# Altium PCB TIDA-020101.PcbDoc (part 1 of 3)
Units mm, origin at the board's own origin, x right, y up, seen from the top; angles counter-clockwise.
Board outline 55 x 55 mm, 4 copper layers (Top Layer 1, Top Layer, Bottom Layer, Bottom Layer 1), stack 1.647 mm thick; 151 components, 88 nets, 395 pads, 362 vias.
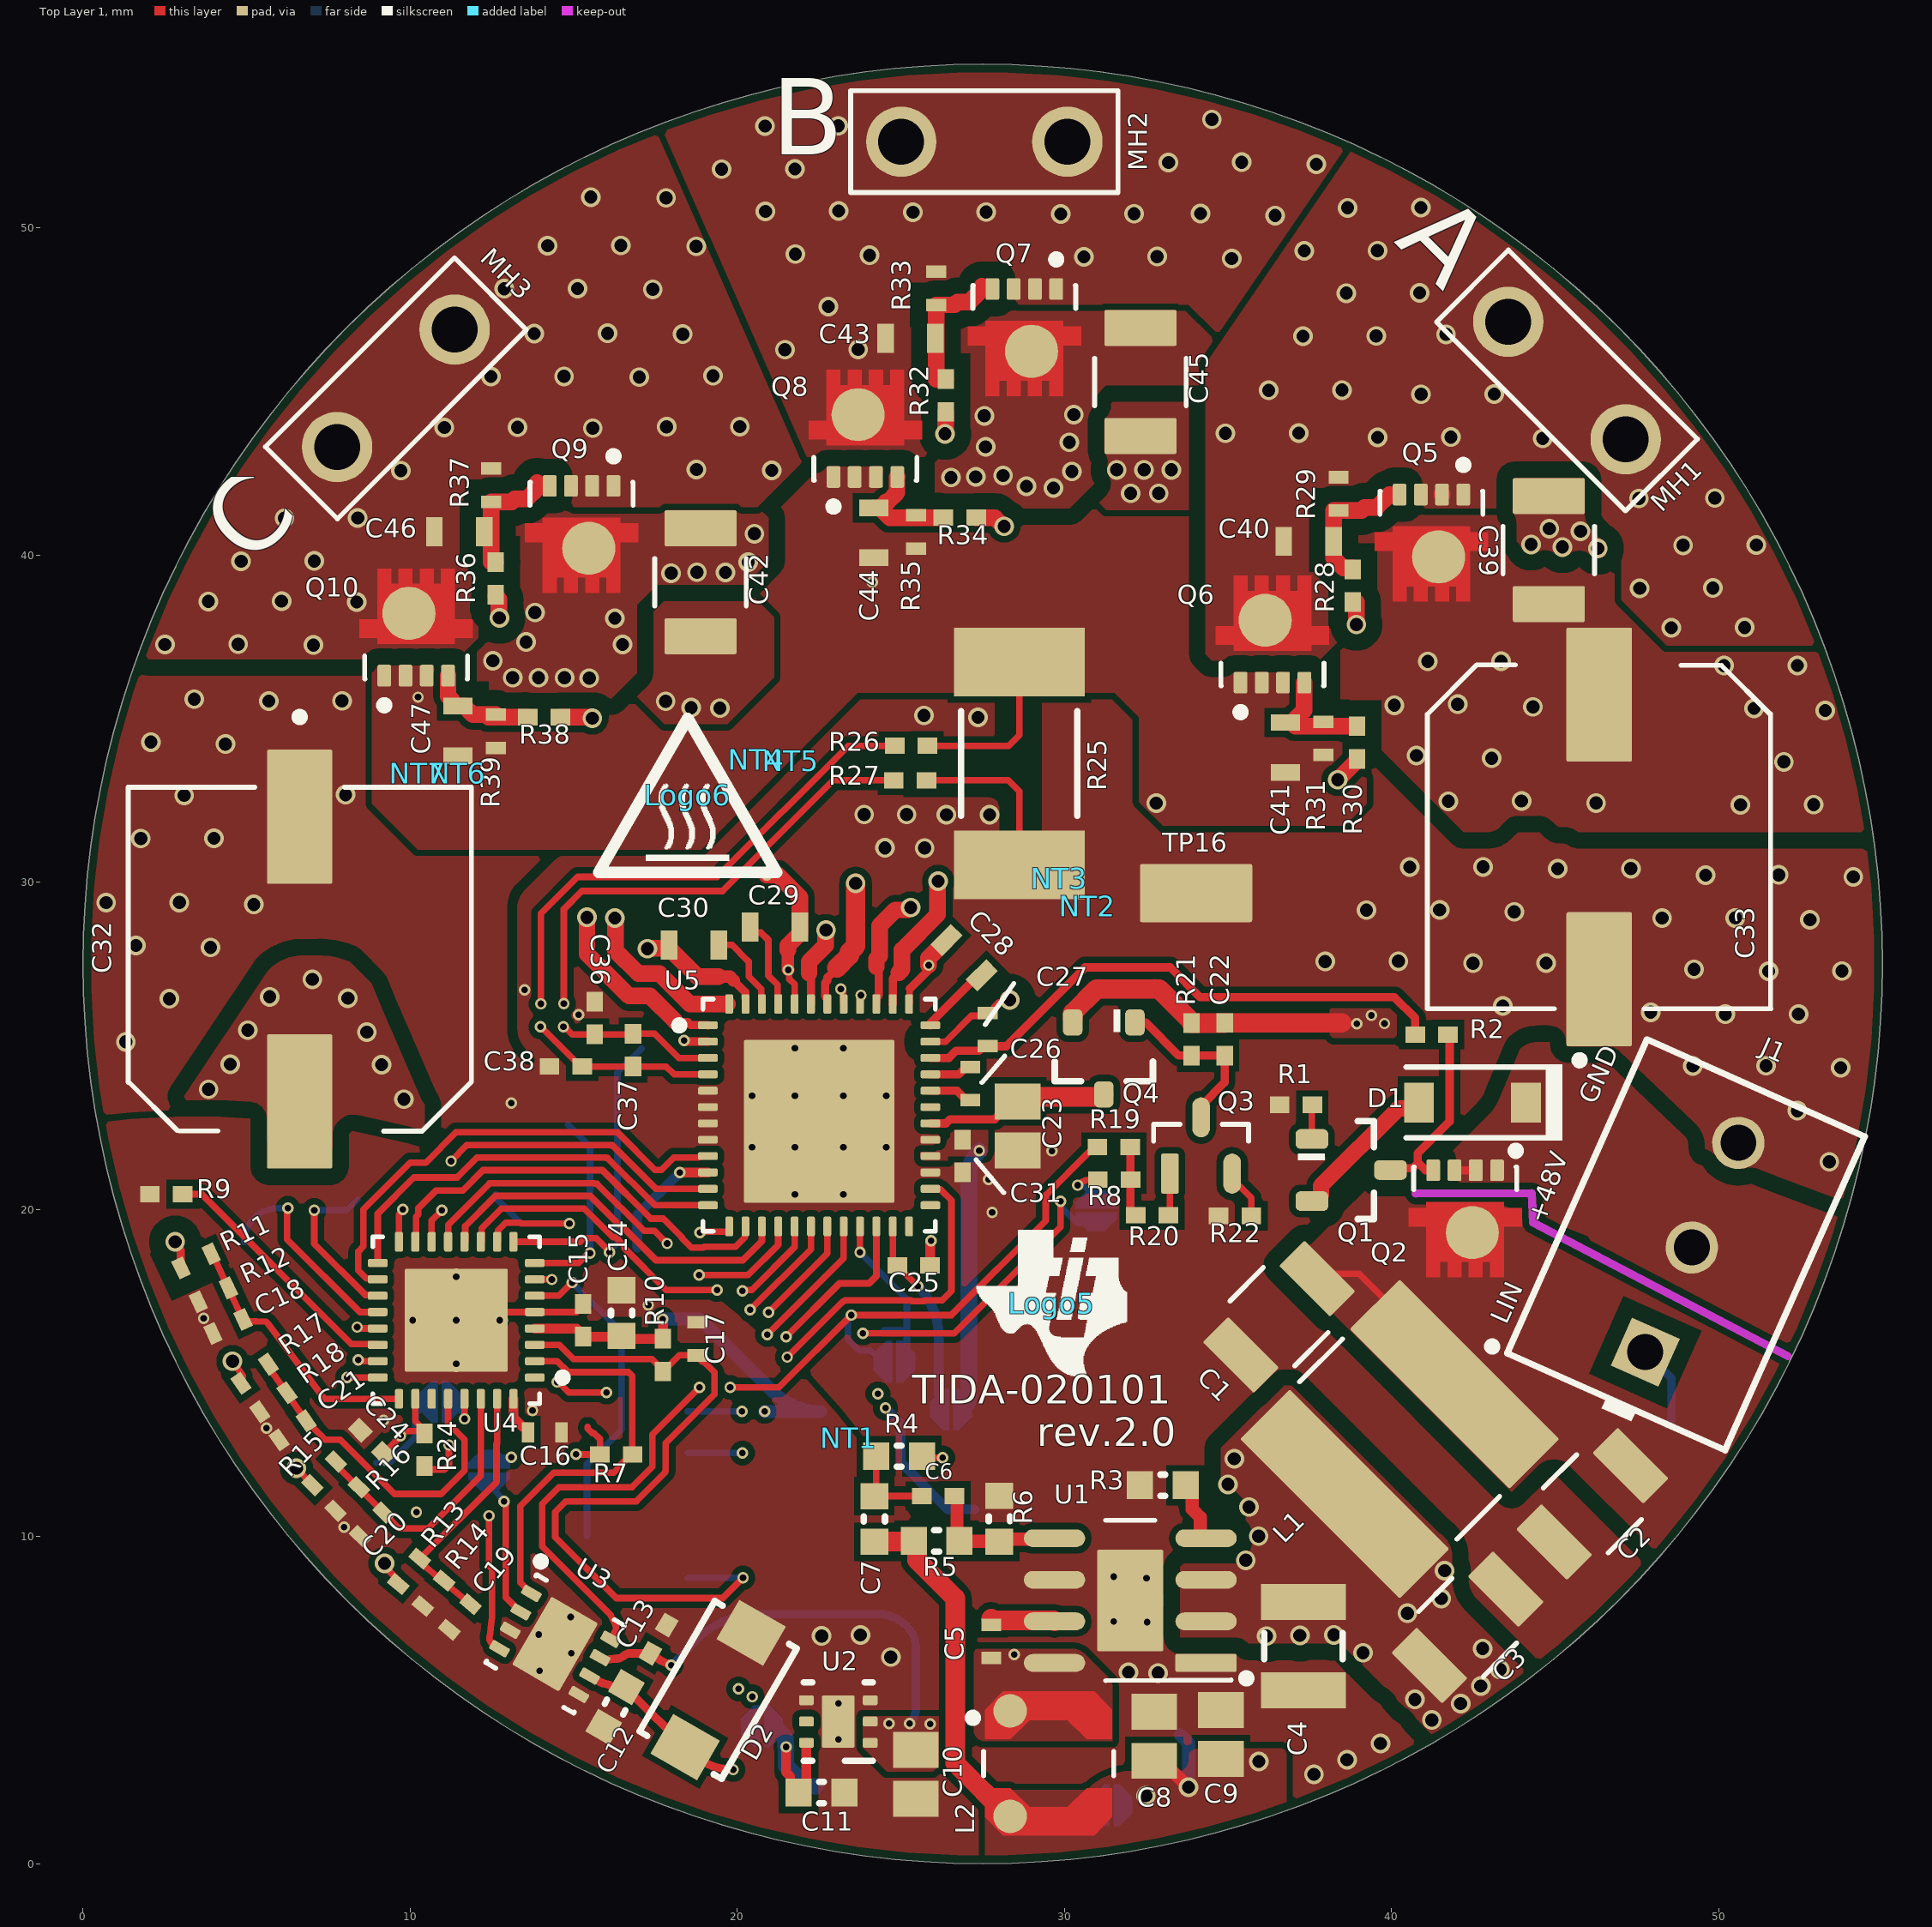
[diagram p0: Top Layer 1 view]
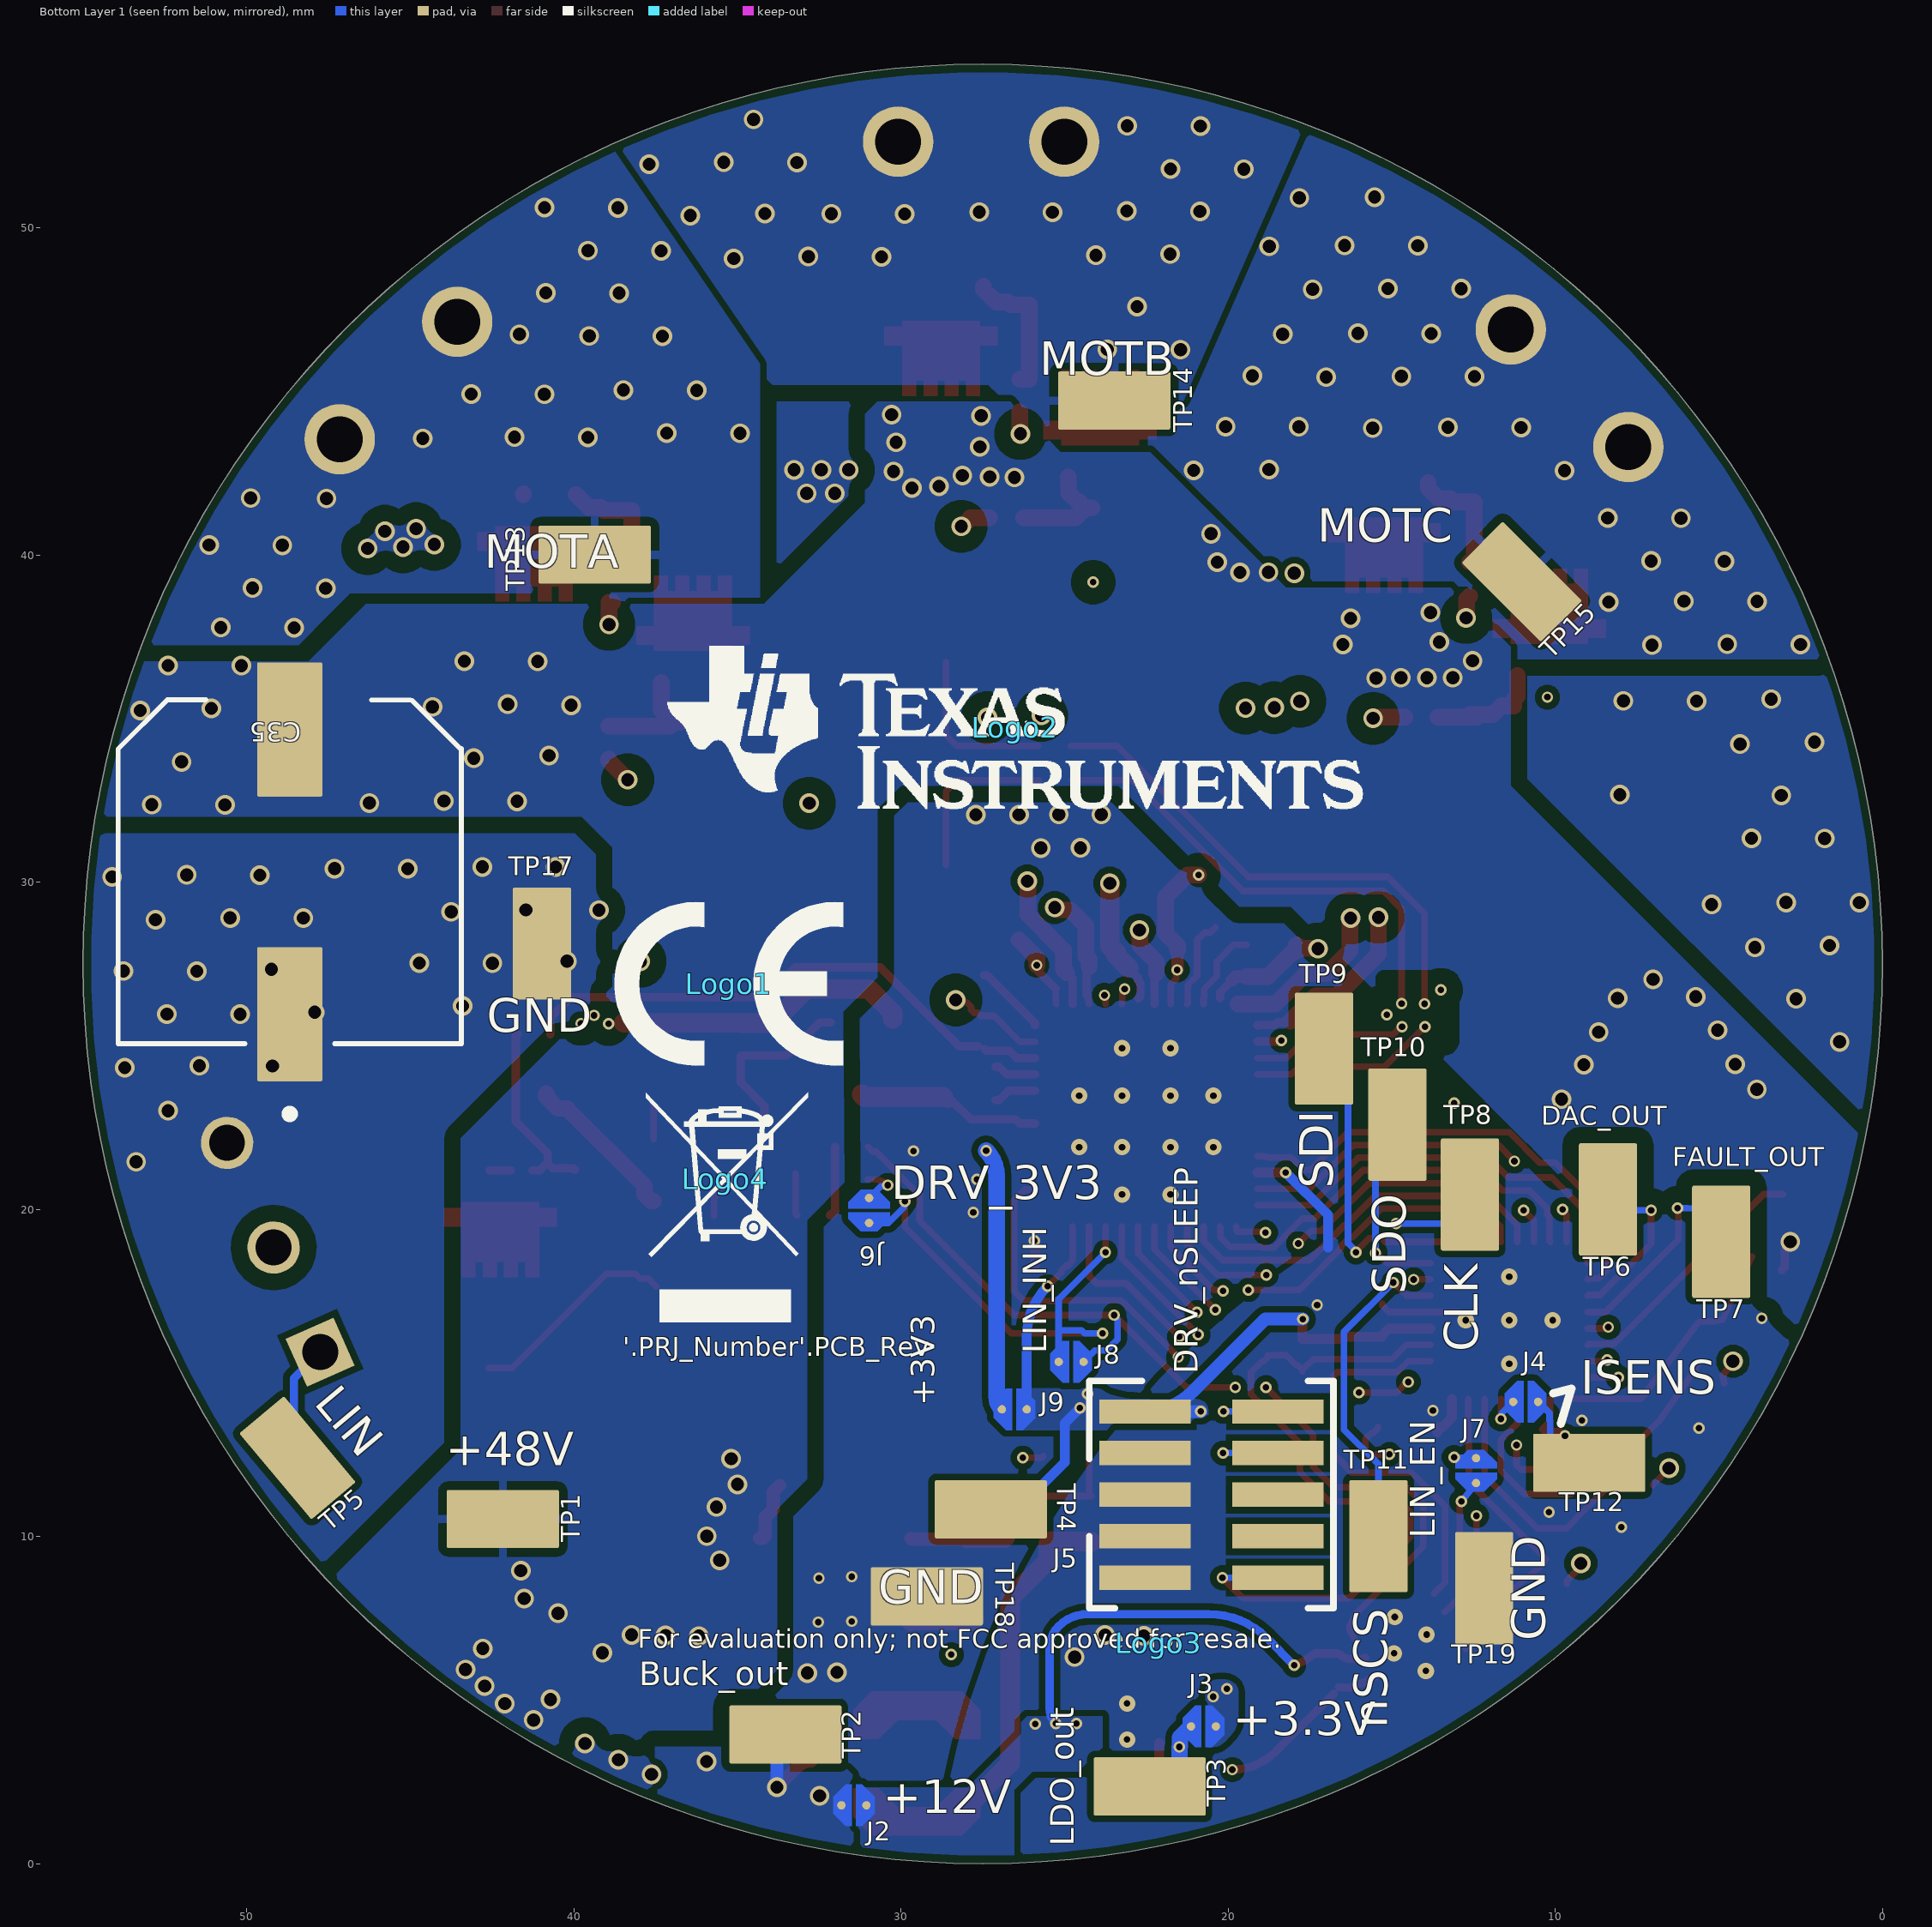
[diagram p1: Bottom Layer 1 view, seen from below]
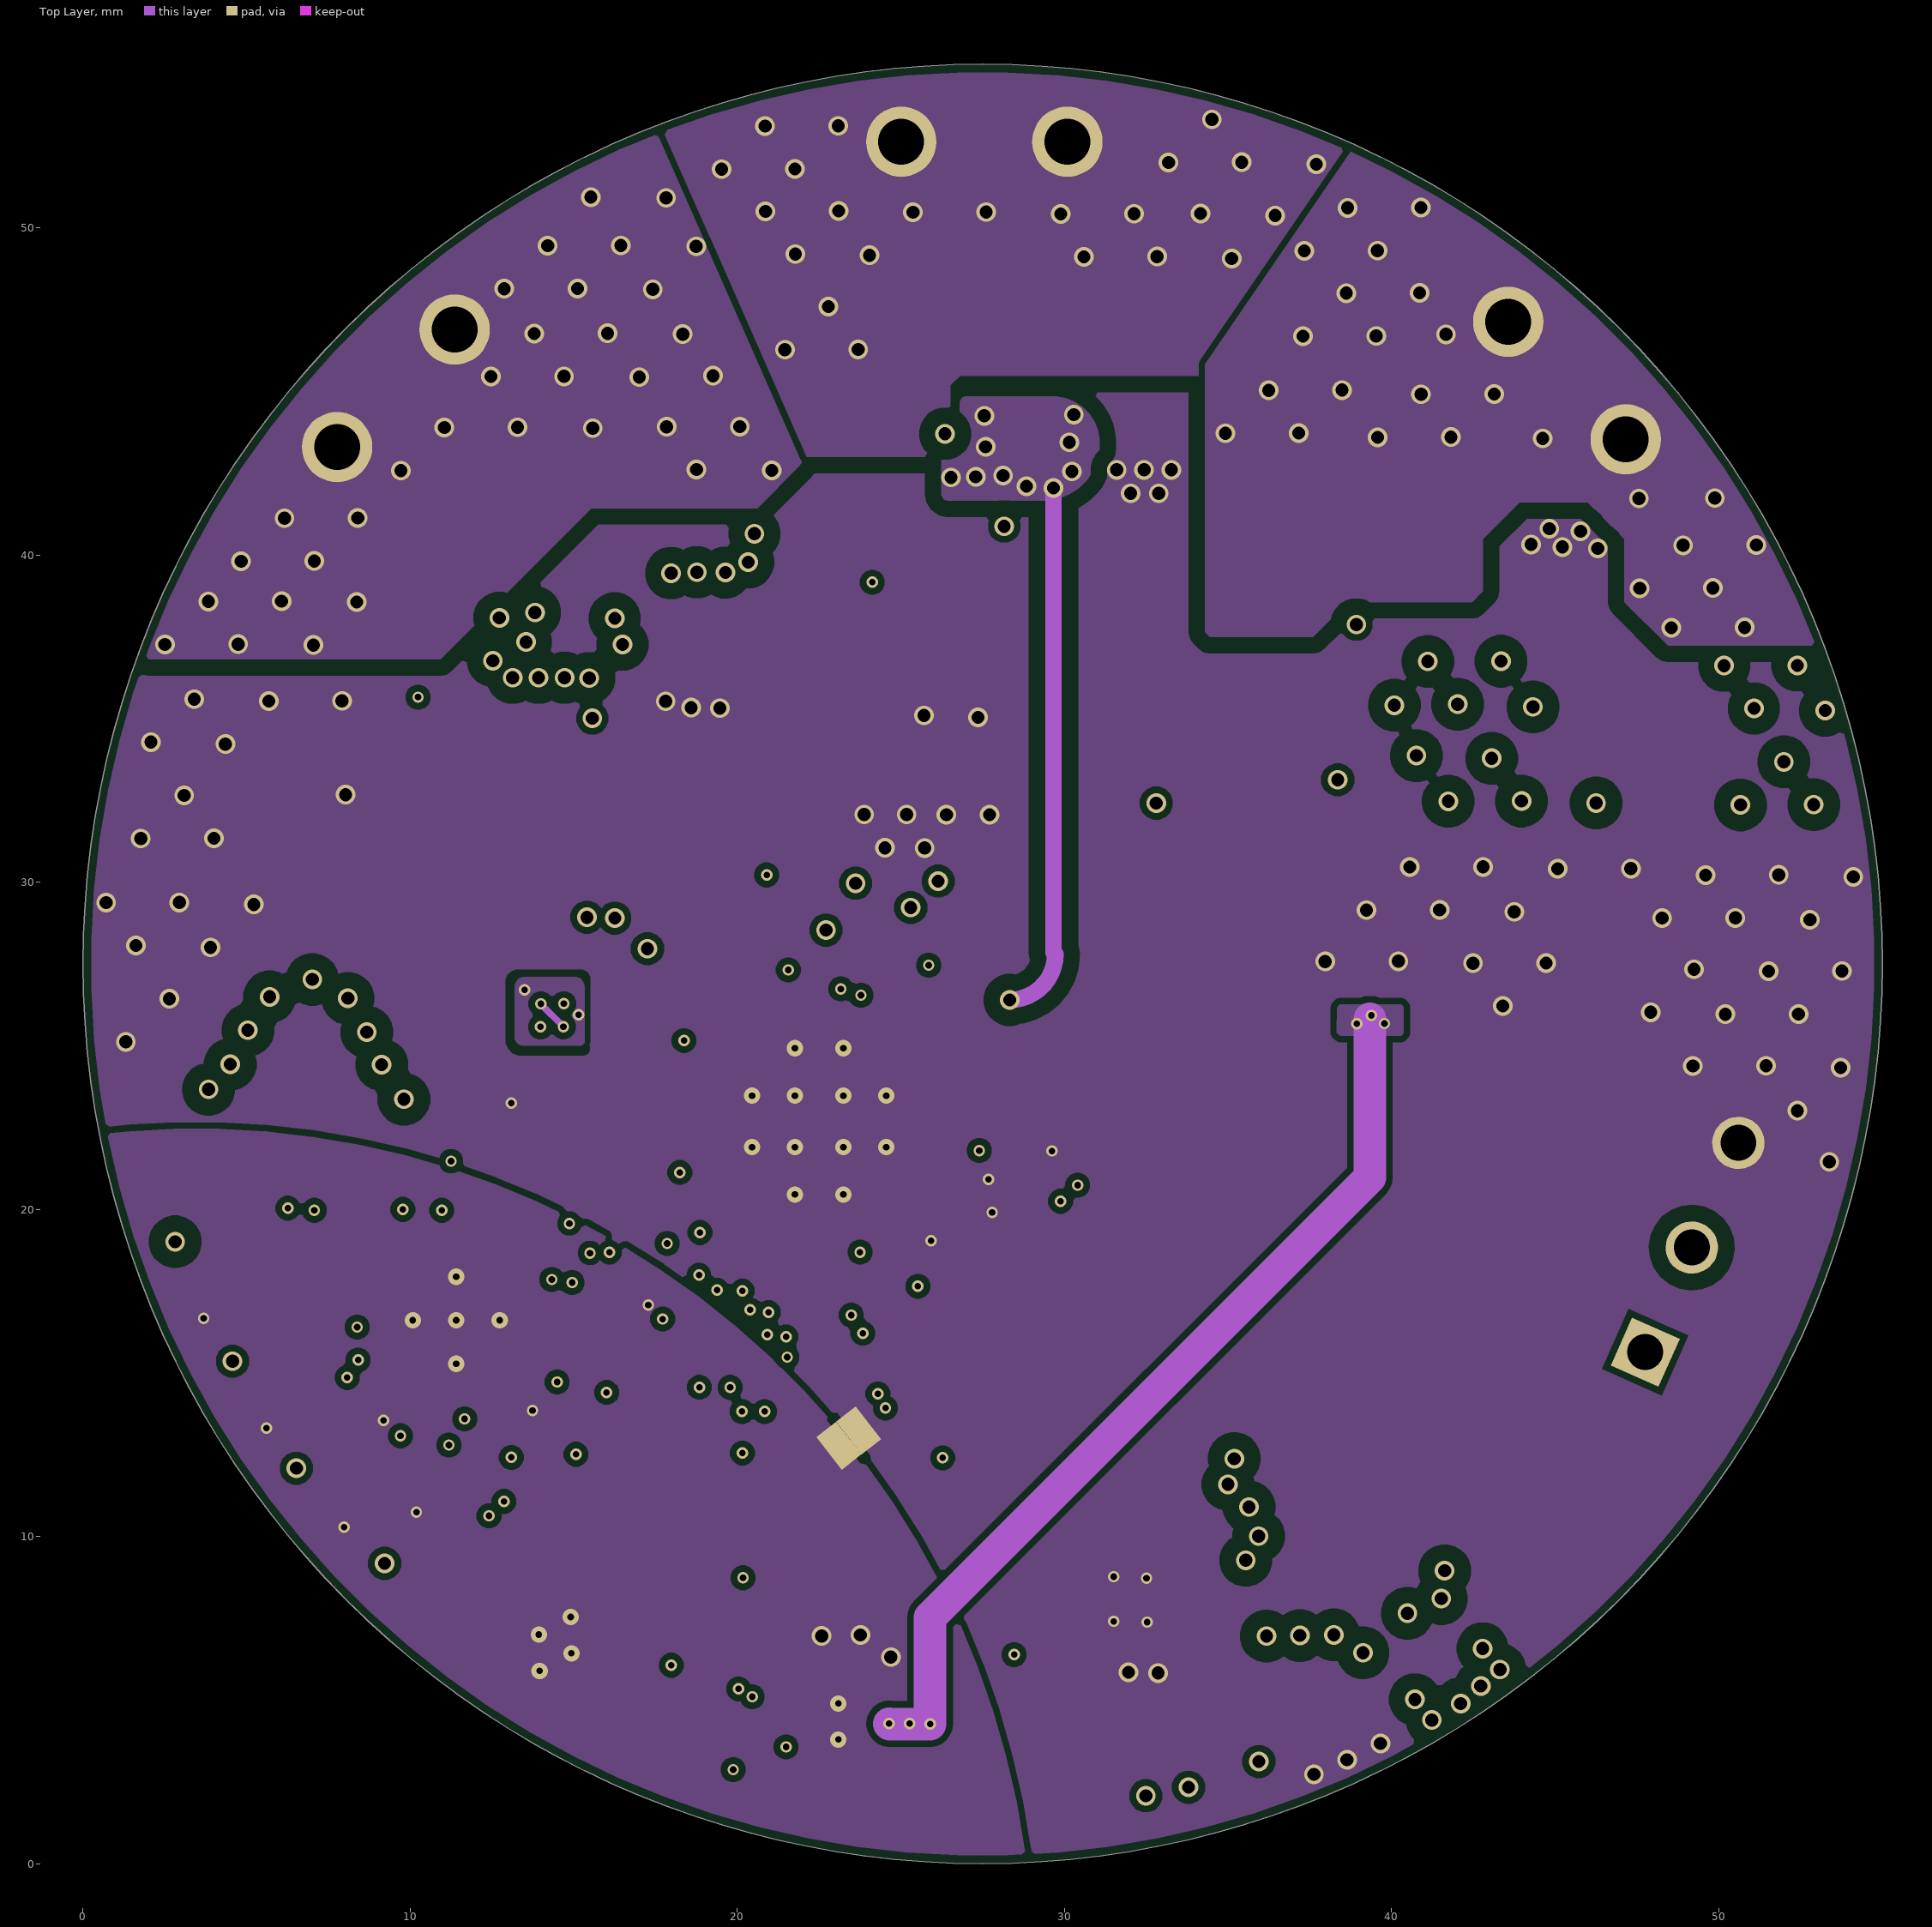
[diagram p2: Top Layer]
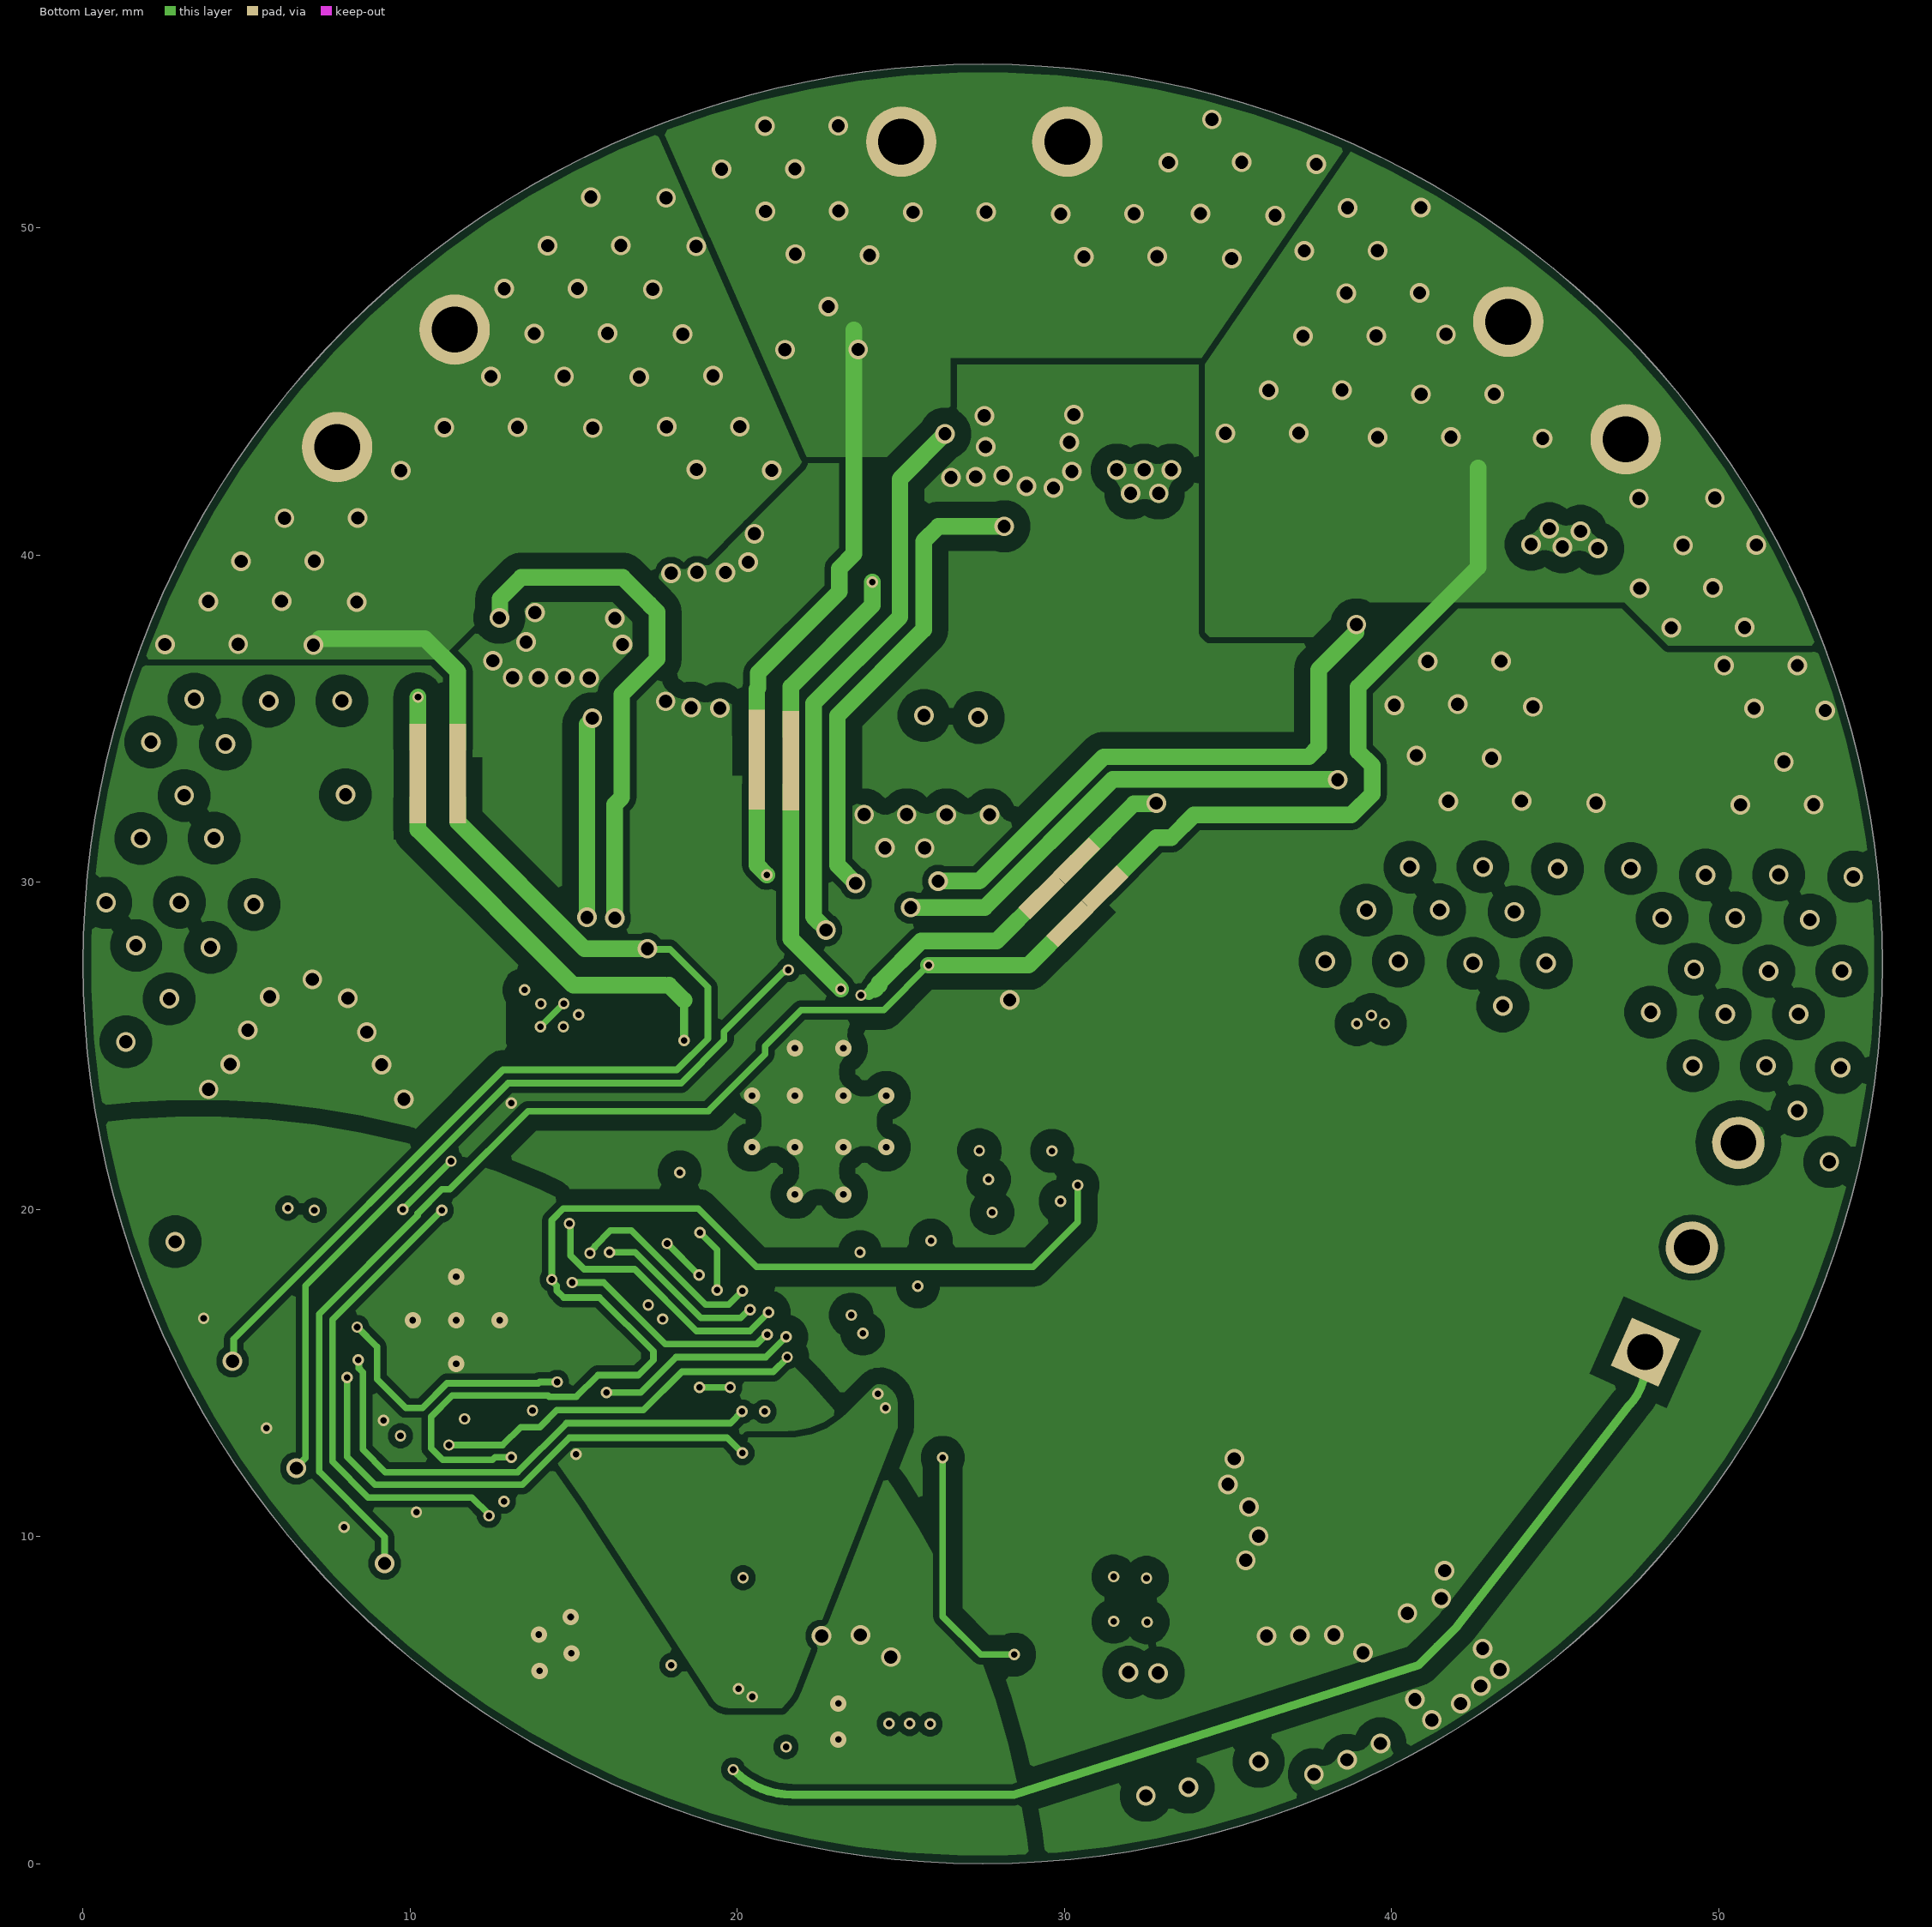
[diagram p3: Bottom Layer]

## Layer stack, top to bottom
Top Solder: solder mask 0.0102, Solder Resist, Dk 3.5
Top Layer 1: signal copper 0.07
Dielectric 1: prepreg 0.203, PP-006, Dk 4.1
Top Layer: signal copper 0.0356
Dielectric1: core 1.03, FR-4 High Tg, Dk 4.8
Bottom Layer: signal copper 0.0356
Dielectric 2: prepreg 0.203, PP-006, Dk 4.1
Bottom Layer 1: signal copper 0.07
Bottom Solder: solder mask 0.0102, Solder Resist, Dk 3.5

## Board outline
27.5,0 cw(c27.5,27.5) 0,27.5 cw(c27.5,27.5) 27.5,55 cw(c27.5,27.5) 55,27.5 cw(c27.5,27.5)

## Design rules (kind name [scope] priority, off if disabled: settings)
AcuteAngle [All] p1: isadvanced=TRUE minimum=4.50000000000000E+0001 checktracksonly=FALSE
AssemblyTestPointUsage [All] p1: isadvanced=TRUE valid=2
AssemblyTestpoint [All] p1: isadvanced=TRUE testpointundercomponent=TRUE minsize=1.016 maxsize=2.54 preferedsize=1.524 minholesize=0 maxholesize=1.016 preferedholesize=0.813 testpointgrid=0.025 usegrid=TRUE gridtolerance=0 allowsidetop=TRUE allowsidebottom=TRUE
BoardOutlineClearance BoardOutlineClearance_MountingHoles [OnCopper and InComponentClass('Mounting Holes')] p1: isadvanced=TRUE gap=0.25 ignorepadtopadclearanceinfootprint=FALSE
BoardOutlineClearance BoardOutlineClearance_Poly [OnCopper and IsPoly] p2: isadvanced=TRUE gap=0.25 ignorepadtopadclearanceinfootprint=FALSE
BoardOutlineClearance [OnCopper and Not InComponentClass('Logo') and not InComponentClass('FiducialMark') and not InRegion(1000,500,4000,800) and not InPoly] p3: isadvanced=TRUE gap=0.25 ignorepadtopadclearanceinfootprint=FALSE
Clearance Clearance_48V [InNetClass('HV_class') vs InNetClass('LV_class')] p1: gap=0.5 ignorepadtopadclearanceinfootprint=TRUE
Clearance Clearance_Keepouts [((IsTrack Or IsArc) And Not InPoly) And IsFree and IsKeepOut vs ((IsTrack Or IsArc) And Not InPoly) And IsFree and IsKeepOut] p2: isadvanced=TRUE gap=0 ignorepadtopadclearanceinfootprint=FALSE
Clearance Clearance_Poly [InPolygon] p3: isadvanced=TRUE gap=0.2 ignorepadtopadclearanceinfootprint=TRUE
Clearance Clearance_FiducialMark [IsKeepOut and InComponentClass('FiducialMark') vs IsPad and InComponentClass('FiducialMark')] p4: isadvanced=TRUE gap=0 ignorepadtopadclearanceinfootprint=FALSE
Clearance Clearance_1 [(ExistsOnLayer('Top Layer') Or ExistsOnLayer('Bottom Layer')) vs (ExistsOnLayer('Top Layer') Or ExistsOnLayer('Bottom Layer'))] p5: gap=0.178 ignorepadtopadclearanceinfootprint=TRUE sourcerule=161 cellrowname=All cellrowtype=0 cellcolname=All cellcoltype=0 innerlayers=TRUE
Clearance Clearance_2 [(ExistsOnLayer('Top Layer 1') Or ExistsOnLayer('Bottom Layer 1')) vs (ExistsOnLayer('Top Layer 1') Or ExistsOnLayer('Bottom Layer 1'))] p6: gap=0.178 ignorepadtopadclearanceinfootprint=TRUE sourcerule=161 cellrowname=All cellrowtype=0 cellcolname=All cellcoltype=0 outerlayers=TRUE
Clearance [All] p7: gap=0.2 ignorepadtopadclearanceinfootprint=TRUE except(0.1: Arc-SMDPad Track-SMDPad; 0.15: SMDPad-SMDPad) ismatrix=TRUE
ComponentClearance ComponentClearance_MountingHoles_FiducialMarks [InComponentClass('Mounting Holes') vs InComponentClass('FiducialMark')] p1: isadvanced=TRUE gap=1.27 collisioncheckmode=3 verticalgap=0.254 showdistances=FALSE
ComponentClearance ComponentClearance_Shunt [InComponentClass('Header') vs InComponentClass('Shunt')] p2: isadvanced=TRUE gap=0 collisioncheckmode=3 verticalgap=0 showdistances=FALSE
ComponentClearance ComponentClearance_Logo [InComponentClass('Logo')] p3: isadvanced=TRUE gap=0.762 collisioncheckmode=3 verticalgap=0.254 showdistances=FALSE
ComponentClearance ComponentClearance_ScrewToNut [(HasFootprint('NY PMS 440 0025 PH')) vs (HasFootprint('Keystone_1902C'))] p4: isadvanced=TRUE gap=0.127 collisioncheckmode=3 verticalgap=0.254 showdistances=FALSE
ComponentClearance ComponentClearance_MountingHoles [InComponentClass('Mounting Holes')] p5: isadvanced=TRUE gap=2.54 collisioncheckmode=3 verticalgap=2540 showdistances=FALSE
ComponentClearance ComponentClearance_SmallPassives [HasFootprint('0201*') or HasFootprint('0402*') or HasFootprint('0508') or HasFootprint('0603*') or HasFootprint('0612') or HasFootprint('0805*') or HasFootprint('0815*') or HasFootprint('0830*') or HasFootprint('1206*') or HasFootprint('1210*') or HasFootprint('1808*') or HasFootprint('1812*') or HasFootprint('1825*') or HasFootprint('2010*') or HasFootprint('2220*') or HasFootprint('2225*') or HasFootprint('2512*') or HasFootprint('2728*') or HasFootprint('3518*') vs HasFootprint('0201*') or HasFootprint('0402*') or HasFootprint('0508') or HasFootprint('0603*') or HasFootprint('0612') or HasFootprint('0805*') or HasFootprint('0815*') or HasFootprint('0830*') or HasFootprint('1206*') or HasFootprint('1210*') or HasFootprint('1808*') or HasFootprint('1812*') or HasFootprint('1825*') or HasFootprint('2010*') or HasFootprint('2220*') or HasFootprint('2225*') or HasFootprint('2512*') or HasFootprint('2728*') or HasFootprint('3518*')] p6: isadvanced=TRUE gap=0.38 collisioncheckmode=3 verticalgap=0.254 showdistances=FALSE
ComponentClearance ComponentClearance_THtoSMT [IsThruComponent vs IsSMTComponent] p7: isadvanced=TRUE gap=0.762 collisioncheckmode=3 verticalgap=0.762 showdistances=FALSE
ComponentClearance ComponentClearance_THtoTH [IsThruComponent vs IsThruComponent] p8: isadvanced=TRUE gap=0.508 collisioncheckmode=3 verticalgap=0.762 showdistances=FALSE
ComponentClearance [All] p9: isadvanced=TRUE gap=0.508 collisioncheckmode=3 verticalgap=0.254 showdistances=FALSE
FabricationTestPointUsage TestPointUsage [All] p1: isadvanced=TRUE valid=2 allowmultiple=FALSE
FabricationTestpoint Testpoint [All] p1: isadvanced=TRUE side=3 testpointundercomponent=TRUE minsize=1.016 maxsize=2.54 preferedsize=1.524 minholesize=0 maxholesize=1.016 preferedholesize=0.813 testpointgrid=0.025 allowsidetop=TRUE allowsidebottom=TRUE usegrid=TRUE gridtolerance=0
FanoutControl Fanout_LCC [IsLCC] p1: isadvanced=TRUE bgadir=Out bgaviamode=Centered fanoutstyle=Auto fanoutdirection=Alternating viagrid=0.025 // Fanout_LCC (Default Rule)
FanoutControl Fanout_BGA [IsBGA] p2: isadvanced=TRUE bgadir=Out bgaviamode=Centered fanoutstyle=Auto fanoutdirection=Alternating viagrid=0.025 // Fanout_BGA (Default Rule)
FanoutControl Fanout_SOIC [IsSOIC] p3: isadvanced=TRUE bgadir=Out bgaviamode=Centered fanoutstyle=Auto fanoutdirection=Alternating viagrid=0.025 // Fanout_SOIC (Default Rule)
FanoutControl Fanout_Small [(CompPinCount < 5)] p4: isadvanced=TRUE bgadir=Out bgaviamode=Centered fanoutstyle=Auto fanoutdirection=OutThenIn viagrid=0.025 // Fanout_Small (Default Rule)
FanoutControl Fanout_Default [All] p5: isadvanced=TRUE bgadir=Out bgaviamode=Centered fanoutstyle=Auto fanoutdirection=Alternating viagrid=0.025 // Fanout_Default (Default Rule)
Height [All] p1: isadvanced=TRUE minheight=0 maxheight=25.4 prefheight=12.7
HoleSize [All] p1: isadvanced=TRUE absolutevalues=TRUE maxlimit=10 minlimit=0.2 maxpercent=80.000 minpercent=20.000
HoleToHoleClearance [All] p1: isadvanced=TRUE gap=0.254 allowstackedmicrovias=TRUE
LayerPairs [All] p1: isadvanced=TRUE enforce=TRUE
MinimumAnnularRing MinimumAnnularRing_ThermalPadVias [IsVia and InAnyComponent] p1: isadvanced=TRUE minimumring=0.074
MinimumAnnularRing [All] p2: isadvanced=TRUE minimumring=0.074
MinimumSolderMaskSliver MinimumSolderMaskSliver_Logo [InComponentClass('Logo') vs InComponentClass('Logo')] p1: isadvanced=TRUE minsoldermaskwidth=0.018
MinimumSolderMaskSliver [All] p2: isadvanced=TRUE minsoldermaskwidth=0.1
NetAntennae [All] p1: isadvanced=TRUE netantennaetolerance=0
PasteMaskExpansion [All] p1: isadvanced=TRUE expansion=0
PlaneClearance [All] p1: isadvanced=TRUE clearance=0.508
PlaneConnect [All] p1: isadvanced=TRUE planeconnectstyle=Direct reliefexpansion=0.254 reliefentries=4 reliefconductorwidth=0.254 reliefairgap=0.254
PolygonConnect [All] p1: connectstyle=Direct reliefconductorwidth=0.254 reliefentries=4 polygonreliefangle="90 Angle" airgapwidth=0.254
RoutingCorners [All] p1: isadvanced=TRUE cornerstyle=45-Degree minsetback=2.54 maxsetback=2.54
RoutingPriority [All] p1: isadvanced=TRUE routingpriority=0
RoutingVias RoutingViaStyle_1 [All] p1: holewidth=0.2 width=0.35 viastyle="Through Hole" minholewidth=0.2 minwidth=0.35 maxholewidth=3 maxwidth=5
ShortCircuit [All] p1: isadvanced=TRUE allowed=FALSE
SilkToSilkClearance SilkToSilkClearance_Pb-FreeLogo [(HasFootprint('Pb-Free_Overlay_Medium') OR HasFootprint('Pb-Free_Overlay_Small')) vs (HasFootprint('Pb-Free_Overlay_Medium') OR HasFootprint('Pb-Free_Overlay_Small'))] p1: isadvanced=TRUE silktosilkclearance=0
SilkToSilkClearance [All] p2: isadvanced=TRUE silktosilkclearance=0.1
SilkToSolderMaskClearance SilkToComponentPadClearance [(IsPad or IsFill or IsRegion) and InAnycomponent] p1: isadvanced=TRUE minsilkscreentomaskgap=0.127 clearancetoexposedcopper=TRUE
SilkToSolderMaskClearance "Silk to Solder Mask Opening" [All] p2: isadvanced=TRUE minsilkscreentomaskgap=0.1 clearancetoexposedcopper=FALSE
SolderMaskExpansion [All] p1: isadvanced=TRUE expansion=0.05 istentingtop=FALSE
SupplyNets "Schematic Supply Nets_103" [InNet('GND')] p1: voltage=0.000
SupplyNets "Schematic Supply Nets_102" [InNet('+3V3')] p2: voltage=0.000
SupplyNets "Schematic Supply Nets_101" [InNet('GND_bridge')] p3: voltage=0.000
SupplyNets "Schematic Supply Nets_100" [InNet('AGND')] p4: voltage=0.000
SupplyNets "Schematic Supply Nets_99" [InNet('VBATT')] p5: voltage=0.000
SupplyNets "Schematic Supply Nets_98" [InNet('+48V')] p6: voltage=0.000
SupplyNets "Schematic Supply Nets_97" [InNet('+3V3_DRV')] p7: voltage=0.000
SupplyNets "Schematic Supply Nets_96" [InNet('+12V')] p8: voltage=0.000
SupplyNets "Schematic Supply Nets_95" [InNet('+3V3_DRV')] p9: isadvanced=TRUE voltage=0.000
SupplyNets "Schematic Supply Nets_94" [InNet('+48V')] p10: isadvanced=TRUE voltage=0.000
SupplyNets "Schematic Supply Nets_93" [InNet('+3V3')] p11: isadvanced=TRUE voltage=0.000
SupplyNets "Schematic Supply Nets_92" [InNet('GND_bridge')] p12: isadvanced=TRUE voltage=0.000
SupplyNets "Schematic Supply Nets_91" [InNet('+12V')] p13: isadvanced=TRUE voltage=0.000
SupplyNets "Schematic Supply Nets_90" [InNet('AGND')] p14: isadvanced=TRUE voltage=0.000
SupplyNets "Schematic Supply Nets_89" [InNet('VBATT')] p15: isadvanced=TRUE voltage=0.000
SupplyNets "Schematic Supply Nets_88" [InNet('GND')] p16: isadvanced=TRUE voltage=0.000
SupplyNets "Schematic Supply Nets_87" [InNet('GND_bridge')] p17: isadvanced=TRUE voltage=0.000
SupplyNets "Schematic Supply Nets_86" [InNet('+3V3_DRV')] p18: isadvanced=TRUE voltage=0.000
SupplyNets "Schematic Supply Nets_85" [InNet('VBATT')] p19: isadvanced=TRUE voltage=0.000
SupplyNets "Schematic Supply Nets_84" [InNet('AGND')] p20: isadvanced=TRUE voltage=0.000
SupplyNets "Schematic Supply Nets_83" [InNet('GND')] p21: isadvanced=TRUE voltage=0.000
SupplyNets "Schematic Supply Nets_82" [InNet('+48V')] p22: isadvanced=TRUE voltage=0.000
SupplyNets "Schematic Supply Nets_81" [InNet('+3V3')] p23: isadvanced=TRUE voltage=0.000
SupplyNets "Schematic Supply Nets_80" [InNet('+12V')] p24: isadvanced=TRUE voltage=0.000
SupplyNets "Schematic Supply Nets_79" [InNet('VBATT')] p25: isadvanced=TRUE voltage=0.000
SupplyNets "Schematic Supply Nets_78" [InNet('+12V')] p26: isadvanced=TRUE voltage=0.000
SupplyNets "Schematic Supply Nets_77" [InNet('GND_bridge')] p27: isadvanced=TRUE voltage=0.000
SupplyNets "Schematic Supply Nets_76" [InNet('+48V')] p28: isadvanced=TRUE voltage=0.000
SupplyNets "Schematic Supply Nets_75" [InNet('+3V3')] p29: isadvanced=TRUE voltage=0.000
SupplyNets "Schematic Supply Nets_74" [InNet('AGND')] p30: isadvanced=TRUE voltage=0.000
SupplyNets "Schematic Supply Nets_73" [InNet('GND')] p31: isadvanced=TRUE voltage=0.000
SupplyNets "Schematic Supply Nets_72" [InNet('+3V3_DRV')] p32: isadvanced=TRUE voltage=0.000
SupplyNets "Schematic Supply Nets_71" [InNet('GND')] p33: isadvanced=TRUE voltage=0.000
SupplyNets "Schematic Supply Nets_70" [InNet('+3V3')] p34: isadvanced=TRUE voltage=0.000
SupplyNets "Schematic Supply Nets_69" [InNet('VBATT')] p35: isadvanced=TRUE voltage=0.000
SupplyNets "Schematic Supply Nets_68" [InNet('+3V3_DRV')] p36: isadvanced=TRUE voltage=0.000
SupplyNets "Schematic Supply Nets_67" [InNet('AGND')] p37: isadvanced=TRUE voltage=0.000
SupplyNets "Schematic Supply Nets_66" [InNet('+48V')] p38: isadvanced=TRUE voltage=0.000
SupplyNets "Schematic Supply Nets_65" [InNet('GND_bridge')] p39: isadvanced=TRUE voltage=0.000
SupplyNets "Schematic Supply Nets_64" [InNet('+12V')] p40: isadvanced=TRUE voltage=0.000
SupplyNets "Schematic Supply Nets_63" [InNet('GND_bridge')] p41: isadvanced=TRUE voltage=0.000
SupplyNets "Schematic Supply Nets_62" [InNet('+12V')] p42: isadvanced=TRUE voltage=0.000
SupplyNets "Schematic Supply Nets_61" [InNet('+3V3')] p43: isadvanced=TRUE voltage=0.000
SupplyNets "Schematic Supply Nets_60" [InNet('+48V')] p44: isadvanced=TRUE voltage=0.000
SupplyNets "Schematic Supply Nets_59" [InNet('VBATT')] p45: isadvanced=TRUE voltage=0.000
SupplyNets "Schematic Supply Nets_58" [InNet('+3V3_DRV')] p46: isadvanced=TRUE voltage=0.000
SupplyNets "Schematic Supply Nets_57" [InNet('GND')] p47: isadvanced=TRUE voltage=0.000
SupplyNets "Schematic Supply Nets_56" [InNet('AGND')] p48: isadvanced=TRUE voltage=0.000
SupplyNets "Schematic Supply Nets_55" [InNet('AGND')] p49: isadvanced=TRUE voltage=0.000
SupplyNets "Schematic Supply Nets_54" [InNet('GND_bridge')] p50: isadvanced=TRUE voltage=0.000
SupplyNets "Schematic Supply Nets_53" [InNet('GND')] p51: isadvanced=TRUE voltage=0.000
SupplyNets "Schematic Supply Nets_52" [InNet('+12V')] p52: isadvanced=TRUE voltage=0.000
SupplyNets "Schematic Supply Nets_51" [InNet('VBATT')] p53: isadvanced=TRUE voltage=0.000
SupplyNets "Schematic Supply Nets_50" [InNet('+48V')] p54: isadvanced=TRUE voltage=0.000
SupplyNets "Schematic Supply Nets_49" [InNet('+3V3_DRV')] p55: isadvanced=TRUE voltage=0.000
SupplyNets "Schematic Supply Nets_48" [InNet('+3V3')] p56: isadvanced=TRUE voltage=0.000
SupplyNets "Schematic Supply Nets_47" [InNet('+3V3_DRV')] p57: isadvanced=TRUE voltage=0.000
SupplyNets "Schematic Supply Nets_46" [InNet('+12V')] p58: isadvanced=TRUE voltage=0.000
SupplyNets "Schematic Supply Nets_45" [InNet('GND')] p59: isadvanced=TRUE voltage=0.000
SupplyNets "Schematic Supply Nets_44" [InNet('+48V')] p60: isadvanced=TRUE voltage=0.000
SupplyNets "Schematic Supply Nets_43" [InNet('AGND')] p61: isadvanced=TRUE voltage=0.000
SupplyNets "Schematic Supply Nets_42" [InNet('VBATT')] p62: isadvanced=TRUE voltage=0.000
SupplyNets "Schematic Supply Nets_41" [InNet('+3V3')] p63: isadvanced=TRUE voltage=0.000
SupplyNets "Schematic Supply Nets_40" [InNet('GND_bridge')] p64: isadvanced=TRUE voltage=0.000
SupplyNets "Schematic Supply Nets_39" [InNet('GND_bridge')] p65: isadvanced=TRUE voltage=0.000
SupplyNets "Schematic Supply Nets_38" [InNet('+3V3')] p66: isadvanced=TRUE voltage=0.000
SupplyNets "Schematic Supply Nets_37" [InNet('VBATT')] p67: isadvanced=TRUE voltage=0.000
SupplyNets "Schematic Supply Nets_36" [InNet('AGND')] p68: isadvanced=TRUE voltage=0.000
SupplyNets "Schematic Supply Nets_35" [InNet('+48V')] p69: isadvanced=TRUE voltage=0.000
SupplyNets "Schematic Supply Nets_34" [InNet('+12V')] p70: isadvanced=TRUE voltage=0.000
SupplyNets "Schematic Supply Nets_33" [InNet('+3V3_DRV')] p71: isadvanced=TRUE voltage=0.000
SupplyNets "Schematic Supply Nets_32" [InNet('GND')] p72: isadvanced=TRUE voltage=0.000
SupplyNets "Schematic Supply Nets_31" [InNet('+48V')] p73: isadvanced=TRUE voltage=0.000
SupplyNets "Schematic Supply Nets_30" [InNet('+12V')] p74: isadvanced=TRUE voltage=0.000
SupplyNets "Schematic Supply Nets_29" [InNet('+3V3')] p75: isadvanced=TRUE voltage=0.000
SupplyNets "Schematic Supply Nets_28" [InNet('AGND')] p76: isadvanced=TRUE voltage=0.000
SupplyNets "Schematic Supply Nets_27" [InNet('VBATT')] p77: isadvanced=TRUE voltage=0.000
SupplyNets "Schematic Supply Nets_26" [InNet('+3V3_DRV')] p78: isadvanced=TRUE voltage=0.000
SupplyNets "Schematic Supply Nets_25" [InNet('GND_bridge')] p79: isadvanced=TRUE voltage=0.000
SupplyNets "Schematic Supply Nets_24" [InNet('GND')] p80: isadvanced=TRUE voltage=0.000
SupplyNets "Schematic Supply Nets_23" [InNet('GND_bridge')] p81: isadvanced=TRUE voltage=0.000
SupplyNets "Schematic Supply Nets_22" [InNet('+3V3')] p82: isadvanced=TRUE voltage=0.000
SupplyNets "Schematic Supply Nets_21" [InNet('+48V')] p83: isadvanced=TRUE voltage=0.000
SupplyNets "Schematic Supply Nets_20" [InNet('VBATT')] p84: isadvanced=TRUE voltage=0.000
SupplyNets "Schematic Supply Nets_19" [InNet('+12V')] p85: isadvanced=TRUE voltage=0.000
SupplyNets "Schematic Supply Nets_18" [InNet('GND')] p86: isadvanced=TRUE voltage=0.000
SupplyNets "Schematic Supply Nets_17" [InNet('+3V3_DRV')] p87: isadvanced=TRUE voltage=0.000
SupplyNets "Schematic Supply Nets_16" [InNet('AGND')] p88: isadvanced=TRUE voltage=0.000
SupplyNets "Schematic Supply Nets_15" [InNet('VBATT')] p89: isadvanced=TRUE voltage=0.000
SupplyNets "Schematic Supply Nets_14" [InNet('+3V3')] p90: isadvanced=TRUE voltage=0.000
SupplyNets "Schematic Supply Nets_13" [InNet('AGND')] p91: isadvanced=TRUE voltage=0.000
SupplyNets "Schematic Supply Nets_12" [InNet('GND')] p92: isadvanced=TRUE voltage=0.000
SupplyNets "Schematic Supply Nets_11" [InNet('GND_bridge')] p93: isadvanced=TRUE voltage=0.000
SupplyNets "Schematic Supply Nets_10" [InNet('+48V')] p94: isadvanced=TRUE voltage=0.000
SupplyNets "Schematic Supply Nets_7" [InNet('+12V')] p95: isadvanced=TRUE voltage=0.000
SupplyNets "Schematic Supply Nets_3" [InNet('+3V3_DRV')] p96: isadvanced=TRUE voltage=0.000
SupplyNets "Schematic Supply Nets_2" [InNet('GND')] p97: isadvanced=TRUE voltage=0.000
SupplyNets "Schematic Supply Nets_9" [InNet('AGND')] p98: isadvanced=TRUE voltage=0.000
SupplyNets "Schematic Supply Nets_8" [InNet('GND_bridge')] p99: isadvanced=TRUE voltage=0.000
SupplyNets "Schematic Supply Nets_6" [InNet('+3V3_DRV')] p100: isadvanced=TRUE voltage=0.000
SupplyNets "Schematic Supply Nets_5" [InNet('VBATT')] p101: isadvanced=TRUE voltage=0.000
SupplyNets "Schematic Supply Nets_4" [InNet('+12V')] p102: isadvanced=TRUE voltage=0.000
SupplyNets "Schematic Supply Nets_1" [InNet('+3V3')] p103: isadvanced=TRUE voltage=0.000
SupplyNets "Schematic Supply Nets" [InNet('+48V')] p104: isadvanced=TRUE voltage=0.000
UnRoutedNet [All] p1: isadvanced=TRUE checkbadconnections=TRUE
UnpouredPolygon [All] p1: isadvanced=TRUE
Width MaxMinWidth_1 [All] p1: isadvanced=TRUE maxlimit=10 minlimit=0.2 preferedwidth=0.2 minimp=50.000000 maximp=50.000000 favimp=50.000000
4 further rules are at their usual default settings.

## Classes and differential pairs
net class LV_class: 12V_Buck +3V3 +3V3_DRV +12V AGND BSL_Invoke BSTA BSTB BSTC CPTH CPTL DAC_OUT DRV_DRVOFF DRV_GVDD DRV_GVDD_SW DRV_nFAULT DRV_nSCS DRV_nSLEEP DRV_SCLK DRV_SDI DRV_SDO DRV_VCP FAULT_OUT FB GHA GHB GHC GLA GLB GLC GND GND_bridge INHA INHB INHC INLA INLB INLC ISENA "ISENA (backup)" LIN LIN_DRV_EN LIN_EN LIN_INH LIN_RXD LIN_TXD M0_nRST NetC5_2 NetC6_2 NetC11_1 NetC16_2 NetC22_2 NetC40_1 NetC41_1 NetC43_1 NetC44_1 NetC46_1 NetC47_1 NetD1_2 NetQ1_1 NetQ1_3 NetQ3_1 NetQ3_2 NetR3_2 SEN_VMOTOR SHA SHB SHC SLA SLB SLC SNA SOA SOB SOC SPA SW SWCLK SWDIO VSENA VSENB VSENC
net class HV_class: +48V MOTA MOTB MOTC VBATT VBATT_2
component class TIDA-020101: C1 C2 C3 C4 C5 C6 C7 C8 C9 C10 C11 C12 C13 C14 C15 C16 C17 C18 C19 C20 C21 C22 C23 C24 C25 C26 C27 C28 C29 C30 C31 C32 C33 C35 C36 C37 C38 C39 C40 C41 C42 C43 C44 C45 C46 C47 D1 D2 J1 J2 J3 J4 J5 J6 J7 J8 J9 L1 L2 MH1 MH2 MH3 NT1 NT2 NT3 NT4 NT5 NT6 NT7 Q1 Q2 Q3 Q4 Q5 Q6 Q7 Q8 Q9 Q10 R1 R2 R3 R4 R5 R6 R7 R8 R9 R10 R11 R12 R13 R14 R15 R16 R17 R18 R19 R20 R21 R22 R24 R25 R26 R27 R28 R29 R30 R31 R32 R33 R34 R35 R36 R37 R38 R39 TP1 TP2 TP3 TP4 TP5 TP6 TP7 TP8 TP9 TP10 TP11 TP12 TP13 TP14 TP15 TP16 TP17 TP18 TP19 U1 U2 U3 U4 U5
component class Logo: Logo2 Logo5
component class TIDA-020101_Hardware: Logo1 Logo2 Logo3 Logo4 Logo5 Logo6 ZZ1 ZZ2 ZZ3 ZZ4
component class AssemblyNote: ZZ1 ZZ2 ZZ3 ZZ4

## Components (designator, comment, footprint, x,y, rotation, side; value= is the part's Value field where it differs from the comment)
C1 "CGA6P1X7R2A106K250AC" FP-CGA6P1X7R2A106K250AC_1210-MFG 36.557,16.716 r45 top value=10µF
C2 "CGA6P1X7R2A106K250AC" FP-CGA6P1X7R2A106K250AC_1210-MFG 46.135,10.999 r45 top value=10µF
C3 "CGA6P1X7R2A106K250AC" FP-CGA6P1X7R2A106K250AC_1210-MFG 42.321,7.223 r225 top value=10µF
C4 "CGA6N3X7R2A225K230AB" 1210_250L 37.301,6.646 r270 top value=2.2uF
C5 "CL05B222JB5NNNC" 0402S 27.76,6.792 r90 top value=2200pF
C6 "CC0402KRX7R9BB101" 0402L 26.135,11.235 r180 top value=100pF
C7 "GRM188R71H222KA01D" 0603L 24.186,10.534 r90 top value=2200pF
C8 "CGA4J3X7R1E225K125AB" 0805L 32.741,3.893 r90 top value=2.2uF
C9 "CGA4J3X7R1E225K125AB" 0805L 34.78,3.948 r90 top value=2.2uF
C10 "GRM21BZ71E106KE15L" 0805L 25.456,2.731 r270 top value=10uF
C11 "GRM188Z71A106MA73D" 0603L 22.569,2.172 r0 top value=10uF
C12 "GRM188R72A221KA01D" 0603L 16.262,4.789 r240 top value=220pF
C13 "CGA2B3X7R1E104K050BB" 0402L 17.591,6.86 r60 top value=0.1uF
C14 "C1608X5R1A106M080AC" 0603L 16.461,16.826 r90 top value=10uF
C15 "CGA2B3X7R1E104K050BB" 0402L 15.285,16.608 r90 top value=0.1uF
C16 "CGA2B1X7S1C474K050BE" 0402S 14.113,13.183 r180 top value=0.47uF
C17 "GRM155R71C103KA01D" 0402S 18.777,16.043 r90 top value=0.01uF
C18 "GRM155R71C103KA01D" 0402S 4.431,16.423 r205 top value=0.01uF
C19 "GRM155R71C103KA01D" 0402S 11.519,7.54 r230 top value=0.01uF
C20 "GRM155R71C103KA01D" 0402S 8.829,10.373 r225 top value=0.01uF
C21 "GRM155R71C103KA01D" 0402S 6.406,13.243 r215 top value=0.01uF
C22 "CGA2B3X7R1E104K050BB" 0402L 34.898,25.198 r270 top value=0.1uF
C23 "GRM21BZ71E106KE15L" 0805L 28.566,22.548 r270 top value=10uF
C24 "CGA2B2X7R1H471K050BA" 0402L 8.827,12.894 r135 top value=470pF
C25 "CGA2B3X7R1E104K050BB" 0402L 25.392,18.282 r0 top value=0.1uF
C26 "C1005X5R1E105K050BC" 0402S 27.117,23.846 r270 top value=1uF
C27 "C1005X5R1E105K050BC" 0402S 27.648,25.497 r90 top value=1uF
C28 "CGA3E1X7R1E105K080AD" 0603S 26.932,27.692 r135 top value=1uF
C29 "CGA3E1X7R1E105K080AD" 0603S 21.15,28.622 r0 top value=1uF
C30 "CGA3E1X7R1E105K080AD" 0603S 18.673,28.081 r180 top value=1uF
C31 "C1005X5R1E105K050BC" 0402L 26.888,21.626 r270 top value=1uF
C32 "B40910A0137M000" FP-B40910A0137M000_SMD2-MFG 6.621,27.647 r270 top value=130µF
C33 "B40910A0137M000" FP-B40910A0137M000_SMD2-MFG 46.343,31.382 r90 top value=130µF
C35 "B40910A0137M000" FP-B40910A0137M000_SMD2-MFG 48.681,30.315 r90 bottom value=130µF
C36 "CGA2B3X7S2A102K050BB" 0402L 15.64,25.847 r90 top value=1000pF
C37 "CGA2B3X7S2A102K050BB" 0402L 16.813,24.865 r270 top value=1000pF
C38 "CGA2B3X7S2A102K050BB" 0402L 14.758,24.365 r180 top value=1000pF
C39 "CGA6P1X7R2A106K250AC" FP-CGA6P1X7R2A106K250AC_1210-MFG 44.805,40.15 r270 top value=10µF
C40 "CGA3E2X7R2A103K080AA" 0603S 37.462,40.416 r180 top value=0.01uF
C41 "CGA3E2X7R2A103K080AA" 0603S 36.753,34.116 r270 top value=0.01uF
C42 "CGA6P1X7R2A106K250AC" FP-CGA6P1X7R2A106K250AC_1210-MFG 18.875,39.166 r90 top value=10µF
C43 "CGA3E2X7R2A103K080AA" 0603S 25.291,46.617 r180 top value=0.01uF
C44 "CGA3E2X7R2A103K080AA" 0603S 24.169,40.676 r270 top value=0.01uF
C45 "CGA6P1X7R2A106K250AC" FP-CGA6P1X7R2A106K250AC_1210-MFG 32.321,45.288 r90 top value=10µF
C46 "CGA3E2X7R2A103K080AA" 0603S 11.501,40.711 r180 top value=0.01uF
C47 "CGA3E2X7R2A103K080AA" 0603S 11.46,34.621 r270 top value=0.01uF
D1 "BAS16D-E3-08" SOD-123 42.473,23.266 r180 top value=100V
D2 "SMA6T68CAY" SMA_Bi 19.413,5.31 r240 top value=58.1V
J1 "0393570003" MOLEX_39357-0003 49.175,18.831 r66 top
J2 "SOLDER JUMPER" SolderJumper_50MIL 31.438,1.783 r180 bottom
J3 "SOLDER JUMPER" SolderJumper_50MIL 20.754,4.195 r180 bottom
J4 "SOLDER JUMPER" SolderJumper_50MIL 10.905,14.117 r180 bottom
J5 "FTSH-105-01-L-DV-K" Samtec_FTSH-105-01-x-DV-K 20.509,11.28 r180 bottom
J6 "SOLDER JUMPER" SolderJumper_50MIL 30.973,19.964 r270 bottom
J7 "SOLDER JUMPER" SolderJumper_50MIL 12.42,12.014 r270 bottom
J8 "SOLDER JUMPER" SolderJumper_50MIL 24.798,15.338 r0 bottom
J9 "SOLDER JUMPER" SolderJumper_50MIL 26.534,13.885 r180 bottom
L1 "74438377022" FP-74438377022_SMD2-MFG 40.243,12.978 r225 top value=2.2uH
L2 "LPS4040-104MRC" FP-LPS4040-104MRC_SMT_IND_3MM9_3MM9-MFG 29.513,3.059 r270 top value=100uH
Logo1 "CE Mark" CE_Mark_5mm 35.26,26.892 r180 bottom
Logo2 "Texas Instruments" TI_Stacked_Overlay_Small 26.508,34.725 r180 bottom
Logo3 "FCC disclaimer" FCC_disclaimer 22.116,6.748 r180 bottom
Logo4 "WEEE logo" WEEE_Minimum 35.371,20.926 r180 bottom
Logo5 "Texas Instruments" TI_Symbol_Overlay_Small 29.606,17.128 r0 top
Logo6 "CAUTION HOT SURFACE" IEC_HotSurface_Small 18.482,32.662 r0 top
MH1 "63824-1" FP-63824-1_CONN_7MM92_3MM11-MFG 45.359,45.332 r135 top
MH2 "63824-1" FP-63824-1_CONN_7MM92_3MM11-MFG 27.548,52.632 r0 top
MH3 "63824-1" FP-63824-1_CONN_7MM92_3MM11-MFG 9.562,45.093 r45 top
NT1 "Net-Tie" Net-Tie_50milWide_30milLong 23.406,13.008 r38 top net-tie
NT2 "Net-Tie" Net-Tie_20milWide_60milLong 30.7,29.262 r45 top net-tie
NT3 "Net-Tie" Net-Tie_20milWide_60milLong 29.842,30.117 r45 top net-tie
NT4 "Net-Tie" Net-Tie_20milWide_60milLong 20.593,33.746 r90 top net-tie
NT5 "Net-Tie" Net-Tie_20milWide_60milLong 21.639,33.712 r90 top net-tie
NT6 "Net-Tie" Net-Tie_20milWide_60milLong 11.455,33.319 r90 top net-tie
NT7 "Net-Tie" Net-Tie_20milWide_60milLong 10.237,33.319 r90 top net-tie
Q1 "BCW60D" SOT-23 38.762,21.201 r0 top value="32 V"
Q2 "NVTFS6H850NTAG" FP-NVTFS6H850NTAG_WDFN8-MFG 42.246,19.723 r180 top
Q3 "SMMBT3904LT3G" FP-SMMBT3904LT3G_SOT23-IPC_C 34.173,21.951 r90 top value=40V
Q4 "TP0610K-T1-GE3" SOT-23L 31.202,24.613 r270 top value=-60V
Q5 "NVTFS6H850NTAG" FP-NVTFS6H850NTAG_WDFN8-MFG 41.215,40.376 r180 top
Q6 "NVTFS6H850NTAG" FP-NVTFS6H850NTAG_WDFN8-MFG 36.355,37.571 r0 top
Q7 "NVTFS6H850NTAG" FP-NVTFS6H850NTAG_WDFN8-MFG 28.772,46.658 r180 top
Q8 "NVTFS6H850NTAG" FP-NVTFS6H850NTAG_WDFN8-MFG 23.912,43.854 r0 top
Q9 "NVTFS6H850NTAG" FP-NVTFS6H850NTAG_WDFN8-MFG 15.238,40.641 r180 top
Q10 "NVTFS6H850NTAG" FP-NVTFS6H850NTAG_WDFN8-MFG 10.182,37.782 r0 top
R1 "CRCW040247K0JNED" 0402L 37.076,23.196 r0 top value=47k
R2 "CRCW040210K0JNED" 0402L 41.221,25.34 r180 top value=10k
R3 "CRCW060388K7FKEA" 0603L 33.005,11.566 r0 top value=88.7k
R4 "RT0603DRE07481KL" 0603L 24.942,12.455 r180 top value=481k
R5 "RC0603FR-07453KL" 0603L 26.092,9.865 r180 top value=453k
R6 "RT0603BRD0750K5L" 0603L 28.01,10.542 r270 top value=50.5k
R7 "CRCW040210K0JNED" 0402L 16.299,12.503 r180 top value=10k
R8 "CRCW04024K70JNED" 0402L 31.519,20.913 r0 top value=4.7k
R9 "CRCW040210K0JNED" 0402L 2.542,20.462 r0 top value=10k
R10 "CRCW040247K0JNED" 0402L 17.727,15.543 r90 top value=47k
R11 "CRCW0402976KFKED" 0402S 3.456,18.424 r205 top value=976k
R12 "CRCW040230K1FKED" 0402S 3.982,17.384 r25 top value=30.1k
R13 "CRCW0402976KFKED" 0402S 9.967,8.935 r230 top value=976k
R14 "CRCW040230K1FKED" 0402S 10.716,8.262 r50 top value=30.1k
R15 "CRCW0402976KFKED" 0402S 7.367,11.929 r225 top value=976k
R16 "CRCW040230K1FKED" 0402S 8.072,11.148 r45 top value=30.1k
R17 "CRCW0402976KFKED" 0402S 5.245,14.975 r215 top value=976k
R18 "CRCW040230K1FKED" 0402S 5.819,14.101 r35 top value=30.1k
R19 "CRCW040210K0JNED" 0402L 31.507,21.908 r180 top value=10k
R20 "CRCW040210K0JNED" 0402L 32.675,19.818 r180 top value=10k
R21 "CRCW0402100KJNED" 0402L 33.88,25.194 r90 top value=100k
R22 "CRCW040210K0JNED" 0402L 35.21,19.801 r180 top value=10k
R24 "CRCW0402160RJNED" 0402L 10.432,12.652 r270 top value=160
R25 "CRE2512-FZ-R005E-3" CRE2512-R5_R9 28.618,33.626 r90 top value=0.005
R26 "CRCW040210R0FKED" 0402L 25.311,34.166 r180 top value=10.0
R27 "CRCW040210R0FKED" 0402L 25.28,33.112 r180 top value=10.0
R28 "CRCW04020000Z0ED" 0402L 38.809,39.058 r90 top value=0
R29 "CRCW0402100KJNED" 0402S 38.377,41.867 r270 top value=100k
R30 "CRCW04020000Z0ED" 0402L 38.939,34.266 r90 top value=0
R31 "CRCW0402100KJNED" 0402S 37.912,34.391 r90 top value=100k
R32 "CRCW04020000Z0ED" 0402L 26.372,44.873 r90 top value=0
R33 "CRCW0402100KJNED" 0402S 26.075,48.15 r270 top value=100k
R34 "CRCW04020000Z0ED" 0402L 26.799,41.138 r180 top value=0
R35 "CRCW0402100KJNED" 0402S 25.459,40.705 r90 top value=100k
R36 "CRCW04020000Z0ED" 0402L 12.615,39.281 r90 top value=0
R37 "CRCW0402100KJNED" 0402S 12.477,42.132 r270 top value=100k
R38 "CRCW04020000Z0ED" 0402L 14.09,35.043 r180 top value=0
R39 "CRCW0402100KJNED" 0402S 12.615,34.609 r90 top value=100k
TP1 "5017" Keystone_5017 42.169,10.534 r180 bottom
TP2 "5017" Keystone_5017 33.53,3.948 r180 bottom
TP3 "5017" Keystone_5017 22.395,2.359 r180 bottom
TP4 "5017" Keystone_5017 27.253,10.83 r180 bottom
TP5 "5017" Keystone_5017 48.444,12.405 r230 bottom
TP6 "5017" Keystone_5017 8.387,20.302 r90 bottom
TP7 "5017" Keystone_5017 4.927,19.009 r90 bottom
TP8 "5017" Keystone_5017 12.607,20.452 r270 bottom
TP9 "5017" Keystone_5017 17.069,24.91 r270 bottom
TP10 "5017" Keystone_5017 14.822,22.589 r270 bottom
TP11 "5017" Keystone_5017 15.403,10.01 r270 bottom
TP12 "5017" Keystone_5017 8.962,12.252 r180 bottom
TP13 "5017" Keystone_5017 39.36,40.01 r180 bottom
TP14 "5017" Keystone_5017 23.481,44.718 r180 bottom
TP15 "5017" Keystone_5017 11.021,39.182 r225 bottom
TP16 "5017" Keystone_5017 34.022,29.668 r180 top
TP17 "5017" Keystone_5017 40.972,28.124 r90 bottom
TP18 "5017" Keystone_5017 29.208,8.17 r180 bottom
TP19 "5017" Keystone_5017 12.172,8.422 r90 bottom
U1 "LM5168PQDDARQ1" DDA0008E-IPC_C 32.01,8.042 r180 top
U2 "TPS7B8133QDRVRQ1" DRV0006A 23.086,4.344 r180 top
U3 "TLIN4029ADRBRQ1" DRB0008J-MFG 14.429,6.716 r330 top
U4 "MSPM0G3507QRHBQ1" RHB0032D-MFG 11.407,16.608 r180 top
U5 "DRV8363RGZRQ1" RGZ0048L-MFG 22.5,22.876 r0 top
ZZ1 "This Assembly Note is for PCB labels only" AssemblyNoteLabel 4.699,100.025 r0 top
ZZ2 "These assemblies are ESD sensitive, ESD precautions shall be observed." AssemblyNote 4.699,97.259 r0 top
ZZ3 "These assemblies must be clean and free from flux and all contaminants. Use of no clean flux is not acceptable." AssemblyNote 4.699,95.01 r0 top
ZZ4 "These assemblies must comply with workmanship standards IPC-A-610 Class 2, unless otherwise specified." AssemblyNote 4.699,92.761 r0 top

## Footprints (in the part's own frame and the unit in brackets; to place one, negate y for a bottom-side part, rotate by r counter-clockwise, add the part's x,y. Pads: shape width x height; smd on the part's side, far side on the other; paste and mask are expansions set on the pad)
0402L [mm] "0402 from SM-752 data"
  rect 0.6x0.5 smd: 1(-0.5,0) 2(0.5,0)
  body extent -0.55,-0.3 0.55,0.3, height 0.6
0402S [mil] "Based on C0402S footprint from PADS legacy"
  rect 15x24 smd: 1(-20,0) 2(20,0)
  body extent -22,-12 22,12, height 24
0603L [mm] "0603 from SM-752 data"
  rect 0.8x0.85 smd: 1(-0.7,0) 2(0.7,0)
  silkscreen extent -0.07,-0.33 0.07,0.33, body extent -0.87,-0.47 0.87,0.47, height 1
0603S [mil]
  rect 20x35 smd: 1(-30,0) 2(30,0)
  body extent -34,-19 34,19, height 39
0805L [mm] "0805 from SM-752 data"
  rect 1.1x1.4 smd: 1(-0.75,0) 2(0.75,0)
  body extent -1.1,-0.72 1.1,0.72, height 1.45
1210_250L [mm] "1210"
  rect 1.1x2.6 smd: 1(-1.35,0) 2(1.35,0)
  silkscreen extent -0.4,-1.2 0.4,1.2, body extent -1.7,-1.35 1.7,1.35, height 2.5
AssemblyNote [mm] "Assembly Note"
AssemblyNoteLabel [mm] "Assembly Note for PCB Labels"
CE_Mark_5mm [mm] "Minimum text height for CE Mark"
  silkscreen extent -3.5,-2.5 3.5,2.5
CRE2512-R5_R9 [mm] "SMD, 2-Leads, Body 6.45x3.35mm, Pitch 6.2mm"
  rect 2.1x4 smd: 1(-3.1,0) 2(3.1,0)
  silkscreen extent -1.6,-1.78 1.6,1.78, body extent -3.32,-1.77 3.32,1.77, height 0.9
DDA0008E-IPC_C [mm]
  rrect18% 1.874x0.542 smd paste+0 mask+0: 1(-2.316,1.905)
  rrect100% 1.874x0.542 smd paste+0 mask+0: 2(-2.316,0.635) 3(-2.316,-0.635) 4(-2.316,-1.905) 5(2.316,-1.905) 6(2.316,-0.635) 7(2.316,0.635) 8(2.316,1.905)
  rrect5% 2.025x3.1 smd paste-1000 mask+0: 9(0,0)
  silkscreen extent -3.67,-2.45 0.75,2.5, body extent -3.35,-2.55 3.35,2.55, height 0.25
DRB0008J-MFG [mm] "Recommended Land Pattern"
  rrect32% 0.6x0.31 smd paste+0 mask+0: 1(-1.4,0.975) 2(-1.4,0.325) 3(-1.4,-0.325) 4(-1.4,-0.975) 5(1.4,-0.975) 6(1.4,-0.325) 7(1.4,0.325) 8(1.4,0.975)
  rrect6% 1.65x2.4 smd paste-1000 mask+0: 9(0,0)
  silkscreen extent -1.76,-1.55 1.55,2.09, body extent -1.5,-1.5 1.5,1.5, height 1
DRV0006A [mm] "SON, 6-Leads, Body 2x2mm, Pitch 0.65mm, Thermal Pad 1.6x1mm, TI Recommended"
  rrect33% 0.45x0.3 smd: 1(-0.975,0.65) 2(-0.975,0) 3(-0.975,-0.65) 4(0.975,-0.65) 5(0.975,0) 6(0.975,0.65)
  rrect14% 1x0.7 on Top Paste: 7(0,0.45) 7(0,-0.45)
  rrect10% 1x1.6 smd paste-0.5: 7(0,0)
  silkscreen extent -1.05,-1.2 1.05,1.2, body extent -1.05,-1.05 1.05,1.05, height 0.81
FCC_disclaimer [mm]
FP-63824-1_CONN_7MM92_3MM11-MFG [mm]
  round 2.15 hole 1.4 paste-2539.97 mask+0: 1(-2.54,0) 1(2.54,0)
  silkscreen extent -4.09,-1.56 4.09,1.56, body extent -3.96,-1.54 3.96,1.54, height 10.88
FP-74438377022_SMD2-MFG [mm] "Recommended Land Pattern"
  rrect5% 2.15x6.9 smd paste+0 mask+0: 1(-2.375,0) 2(2.375,0)
  silkscreen extent -4.12,-3.4 0.92,3.4, body extent -3.3,-3.3 3.3,3.3, height 3.1
FP-B40910A0137M000_SMD2-MFG [mm] "Recommended Land Pattern"
  rrect5% 4.1x2 smd paste+0 mask+0: 1(-4.35,0) 2(4.35,0)
  silkscreen extent -7.52,-5.25 5.26,5.25, body extent -6,-5.15 6,5.15, height 16.8
FP-CGA6P1X7R2A106K250AC_1210-MFG [mm] "Recommended Land Pattern"
  rrect9% 1.1x2.2 smd paste+0 mask+0: 1(-1.65,0) 2(1.65,0)
  silkscreen extent -0.72,-1.4 0.72,1.4, body extent -1.6,-1.25 1.6,1.25, height 2.81
FP-LPS4040-104MRC_SMT_IND_3MM9_3MM9-MFG [mm] "Recommended Land Pattern"
  round 1.026 smd paste+0 mask+0: 1(-1.611,-1.175) 2(1.611,-1.175)
  Top Layer 1 region: 2.2,-1.395 2.2,1.395 1.64,1.945 0.75,1.945 0.75,1.17 1.33,0.575 1.33,-0.575 0.75,-1.17 0.75,-1.945 1.64,-1.945
  Top Layer 1 region: -2.2,-1.395 -2.2,1.395 -1.64,1.945 -0.75,1.945 -0.75,1.17 -1.33,0.575 -1.33,-0.575 -0.75,-1.17 -0.75,-1.945 -1.64,-1.945
  silkscreen extent -1.52,-2.44 0.37,1.99, body extent -2.3,-2.15 2.3,2.15, height 0.25
FP-NVTFS6H850NTAG_WDFN8-MFG [mm] "Recommended Land Pattern"
  rrect24% 0.42x0.66 smd paste+0 mask+0: 1(-0.975,-1.47) 2(-0.325,-1.47) 3(0.325,-1.47) 4(0.975,-1.47)
  round 1.623 smd paste+0 mask+0: 5-6-7-8(-0.221,0.434)
  Top Layer 1 region: -1.73,-0.32 -1.185,-0.32 -1.185,-0.5 1.185,-0.5 1.185,-0.32 1.73,-0.32 1.73,0.25 1.185,0.25 1.185,1.8 0.765,1.8 0.765,1.33 0.535,1.33 0.535,1.8 0.115,1.8 0.115,1.33 -0.115,1.33 -0.115,1.8 -0.535,1.8 -0.535,1.33 -0.765,1.33 -0.765,1.8 -1.185,1.8 -1.185,0.25 -1.73,0.25 -1.73,-0.32
  silkscreen extent -1.67,-2.19 1.58,-0.88, body extent -1.65,-1.65 1.65,1.65, height 0.85
FP-SMMBT3904LT3G_SOT23-IPC_C [mm]
  rrect19% 1.224x0.538 smd paste+0 mask+0: 1(-0.86,0.95)
  rrect100% 1.224x0.538 smd paste+0 mask+0: 2(-0.86,-0.95) 3(0.86,0)
  silkscreen extent 0.13,-1.45 0.65,1.45, body extent -1.57,-1.55 1.57,1.55, height 0.25
IEC_HotSurface_Small [mm]
  silkscreen extent -2.72,-2.36 2.72,2.35
Keystone_5017 [mm] "PC Test Point, SMT"
  rrect6% 3.43x1.78 smd: 1(0,0)
  body extent -1.35,-0.51 1.35,0.51, height 1.51
MOLEX_39357-0003 [mm] "Terminal Block, 3.5 mm, 3x1, TH"
  rect 1.6x1.6 hole 1.1: 1(-3.5,0)
  round 1.6 hole 1.1: 2(0,0) 3(3.5,0)
  silkscreen extent -5.61,-3.45 5.25,3.84, body extent -5.25,-3.45 5.16,3.84, height 8.51
Net-Tie_20milWide_60milLong [mil] "20mil net tie, no solder mask opening, no solder paste"
  rect 60x20 on Mid2 paste-10 mask-10: 1(-30,0) 2(30,0)
Net-Tie_50milWide_30milLong [mil] "50mil net tie, no solder mask opening, no solder paste"
  rect 30x50 on Mid1 paste-20 mask-20: 1(-15,0) 2(15,0)
RGZ0048L-MFG [mm]
  rrect42% 0.6x0.24 smd paste+0 mask+0: 1(-3.4,2.75) 2(-3.4,2.25) 3(-3.4,1.75) 4(-3.4,1.25) 5(-3.4,0.75) 6(-3.4,0.25) 7(-3.4,-0.25) 8(-3.4,-0.75) 9(-3.4,-1.25) 10(-3.4,-1.75) 11(-3.4,-2.25) 12(-3.4,-2.75) 25(3.4,-2.75) 26(3.4,-2.25) 27(3.4,-1.75) 28(3.4,-1.25) 29(3.4,-0.75) 30(3.4,-0.25) 31(3.4,0.25) 32(3.4,0.75) 33(3.4,1.25) 34(3.4,1.75) 35(3.4,2.25) 36(3.4,2.75)
  rrect42% 0.24x0.6 smd paste+0 mask+0: 13(-2.75,-3.4) 14(-2.25,-3.4) 15(-1.75,-3.4) 16(-1.25,-3.4) 17(-0.75,-3.4) 18(-0.25,-3.4) 19(0.25,-3.4) 20(0.75,-3.4) 21(1.25,-3.4) 22(1.75,-3.4) 23(2.25,-3.4) 24(2.75,-3.4) 37(2.75,3.4) 38(2.25,3.4) 39(1.75,3.4) 40(1.25,3.4) 41(0.75,3.4) 42(0.25,3.4) 43(-0.25,3.4) 44(-0.75,3.4) 45(-1.25,3.4) 46(-1.75,3.4) 47(-2.25,3.4) 48(-2.75,3.4)
  rrect2% 4.6x4.975 smd paste-1000 mask+0: 49(0,-0.188)
  silkscreen extent -4.4,-3.55 3.55,3.55, body extent -3.8,-3.8 3.8,3.8, height 0.25
RHB0032D-MFG [mm]
  rrect40% 0.6x0.25 smd paste+0 mask+0: 1(-2.4,1.75) 2(-2.4,1.25) 3(-2.4,0.75) 4(-2.4,0.25) 5(-2.4,-0.25) 6(-2.4,-0.75) 7(-2.4,-1.25) 8(-2.4,-1.75) 17(2.4,-1.75) 18(2.4,-1.25) 19(2.4,-0.75) 20(2.4,-0.25) 21(2.4,0.25) 22(2.4,0.75) 23(2.4,1.25) 24(2.4,1.75)
  rrect40% 0.25x0.6 smd paste+0 mask+0: 9(-1.75,-2.4) 10(-1.25,-2.4) 11(-0.75,-2.4) 12(-0.25,-2.4) 13(0.25,-2.4) 14(0.75,-2.4) 15(1.25,-2.4) 16(1.75,-2.4) 25(1.75,2.4) 26(1.25,2.4) 27(0.75,2.4) 28(0.25,2.4) 29(-0.25,2.4) 30(-0.75,2.4) 31(-1.25,2.4) 32(-1.75,2.4)
  rrect3% 3.15x3.15 smd paste-1000 mask+0: 33(0,0)
  silkscreen extent -3.38,-2.55 2.55,2.55, body extent -2.8,-2.8 2.8,2.8, height 0.25
Samtec_FTSH-105-01-x-DV-K [mm] "Header(Shrouded), 1.27mm, 5x2, SMT"
  rect 2.79x0.74 smd: 1(-2.035,2.54) 2(2.035,2.54) 3(-2.035,1.27) 4(2.035,1.27) 5(-2.035,0) 6(2.035,0) 7(-2.035,-1.27) 8(2.035,-1.27) 9(-2.035,-2.54) 10(2.035,-2.54)
  silkscreen extent -3.73,-3.48 3.73,3.48, body extent -2.92,-3.18 2.92,3.17, height 6.13
SMA_Bi [mm] "SMD, 2-Leads, Body 4.275x2.575mm"
  rect 1.4x1.64 smd: 1(-2.015,0) 2(2.015,0)
  silkscreen extent -2.3,-1.45 2.3,1.45, body extent -2.52,-1.45 2.52,1.45, height 2.65
SOD-123 [mm] "On Semi recommended land pattern"
  rect 0.915x1.22 smd: 1(-1.637,0) 2(1.637,0)
  silkscreen extent -2.74,-1.17 2.03,1.17, body extent -1.93,-0.9 1.93,0.9, height 1.35
SolderJumper_50MIL [mil]
  round 10 smd paste-40: 1(-15,0) 2(15,0)
  Top Layer 1 region: 2.5,25 2.5,-25 10,-25 25,-10 25,10 10,25
  Top Layer 1 region: -2.5,25 -2.5,-25 -10,-25 -25,-10 -25,10 -10,25
SOT-23 [mm] "SOT23, 3-Leads, Body 2.9x1.3mm, Pitch 0.95mm, Lead Span 2.5mm, IPC Medium Density"
  rrect50% 1x0.6 smd: 1(-1.2,0.95) 2(-1.2,-0.95) 3(1.2,0)
  silkscreen extent -1.63,-1.5 0.7,1.5, body extent -1.16,-1.45 1.21,1.45, height 1
SOT-23L [mm] "SOT23, 3-Leads, Body 2.9x1.3mm, Pitch 0.95mm, Lead Span 2.5mm, IPC High Density"
  rrect50% 0.8x0.6 smd: 1(-1.1,0.95) 2(-1.1,-0.95) 3(1.1,0)
  silkscreen extent -1.5,-1.5 0.7,1.5, body extent -1.16,-1.45 1.21,1.45, height 1
TI_Stacked_Overlay_Small [mm]
  silkscreen extent -10.63,-2.49 10.63,2.49
TI_Symbol_Overlay_Small [mm]
  silkscreen extent -2.3,-2.23 2.3,2.24
WEEE_Minimum [mm] "WEEElie bin"
  silkscreen extent -2.42,-4.38 2.52,2.65

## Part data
C1 C2 C3 C39 C42 C45: library part CMP-0125410-1, "10 µF ±10% 100V Ceramic Capacitor X7R 1210 (3225 Metric)", Digikey Part Number=445-CGA6P1X7R2A106K250ACCT-ND, Manufacturer=TDK, Mouser Part Number=810-CGA6P1X7R2A106K2, Operating Temperature Range="-55°C to +125°C", TempCo=15%, Temperature Characteristic=X7R, Tolerance_%=10%, ValueDisplayed=10uF
C4: library part CMP-0009152-2, "CAP, CERM, 2.2 uF, 100 V, +/- 10%, X7R, AEC-Q200 Grade 1,", Cap_Case=1210_250, Manufacturer=TDK, Supplier Part Number 1=445-5866-1-ND, TempCo=X7R, Tolerance_%=10%, Value1="0.00173 ohm", Value2=100V, ValueDisplayed=2.2uF
C5: library part CMP-0006344-2, "CAP, CERM, 2200 pF, 50 V, +/- 5%, X7R, 0402", Cap_Case=0402, Manufacturer="Samsung Electro-Mechanics", Supplier Part Number 1=1276-1532-1-ND, TempCo=X7R, Tolerance_%=5%, Value1=Unknown, Value2=50V, ValueDisplayed=2200pF
C6: library part CMP-0006305-2, "CAP, CERM, 100 pF, 50 V, +/- 10%, X7R, 0402", Cap_Case=0402, Manufacturer="Yageo America", Supplier Part Number 1=311-1419-1-ND, TempCo=X7R, Tolerance_%=10%, Value1=Unknown, Value2=50V, ValueDisplayed=100pF
C7: library part CMP-0007443-4, "CAP, CERM, 2200 pF, 50 V, +/- 10%, X7R, 0603", Cap_Case=0603, Manufacturer=MuRata, Supplier Part Number 1=490-1500-1-ND, TempCo=X7R, Tolerance_%=10%, Value1=Unknown, Value2=50V, ValueDisplayed=2200pF
C8 C9: library part CMP-0007975-2, "CAP, CERM, 2.2 uF, 25 V, +/- 10%, X7R, AEC-Q200 Grade 1, 0805", Cap_Case=0805, Manufacturer=TDK, Supplier Part Number 1=445-6965-1-ND, TempCo=X7R, Tolerance_%=10%, Value1=Unknown, Value2=25V, ValueDisplayed=2.2uF
C10 C23: library part CMP-0008378-2, "CAP, CERM, 10 uF, 25 V, +/- 10%, X7R, 0805", Cap_Case=0805, Manufacturer=MuRata, Supplier Part Number 1=81-GRM21BZ71E106KE5L, TempCo=X7R, Tolerance_%=10%, Value1=Unknown, Value2=25V, ValueDisplayed=10uF
C11: library part CMP-0007497-5, "CAP, CERM, 10 uF, 10 V, +/- 20%, X7R, 0603", Cap_Case=0603, Manufacturer=MuRata, Supplier Part Number 1=81-GRM188Z71A106MA3D, TempCo=X7R, Tolerance_%=20%, Value1=Unknown, Value2=10V, ValueDisplayed=10uF
C12: library part CMP-0007474-4, "CAP, CERM, 220 pF, 100 V, +/- 10%, X7R, 0603", Cap_Case=0603, Manufacturer=MuRata, Supplier Part Number 1=490-1460-1-ND, TempCo=X7R, Tolerance_%=10%, Value1=Unknown, Value2=100V, ValueDisplayed=220pF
